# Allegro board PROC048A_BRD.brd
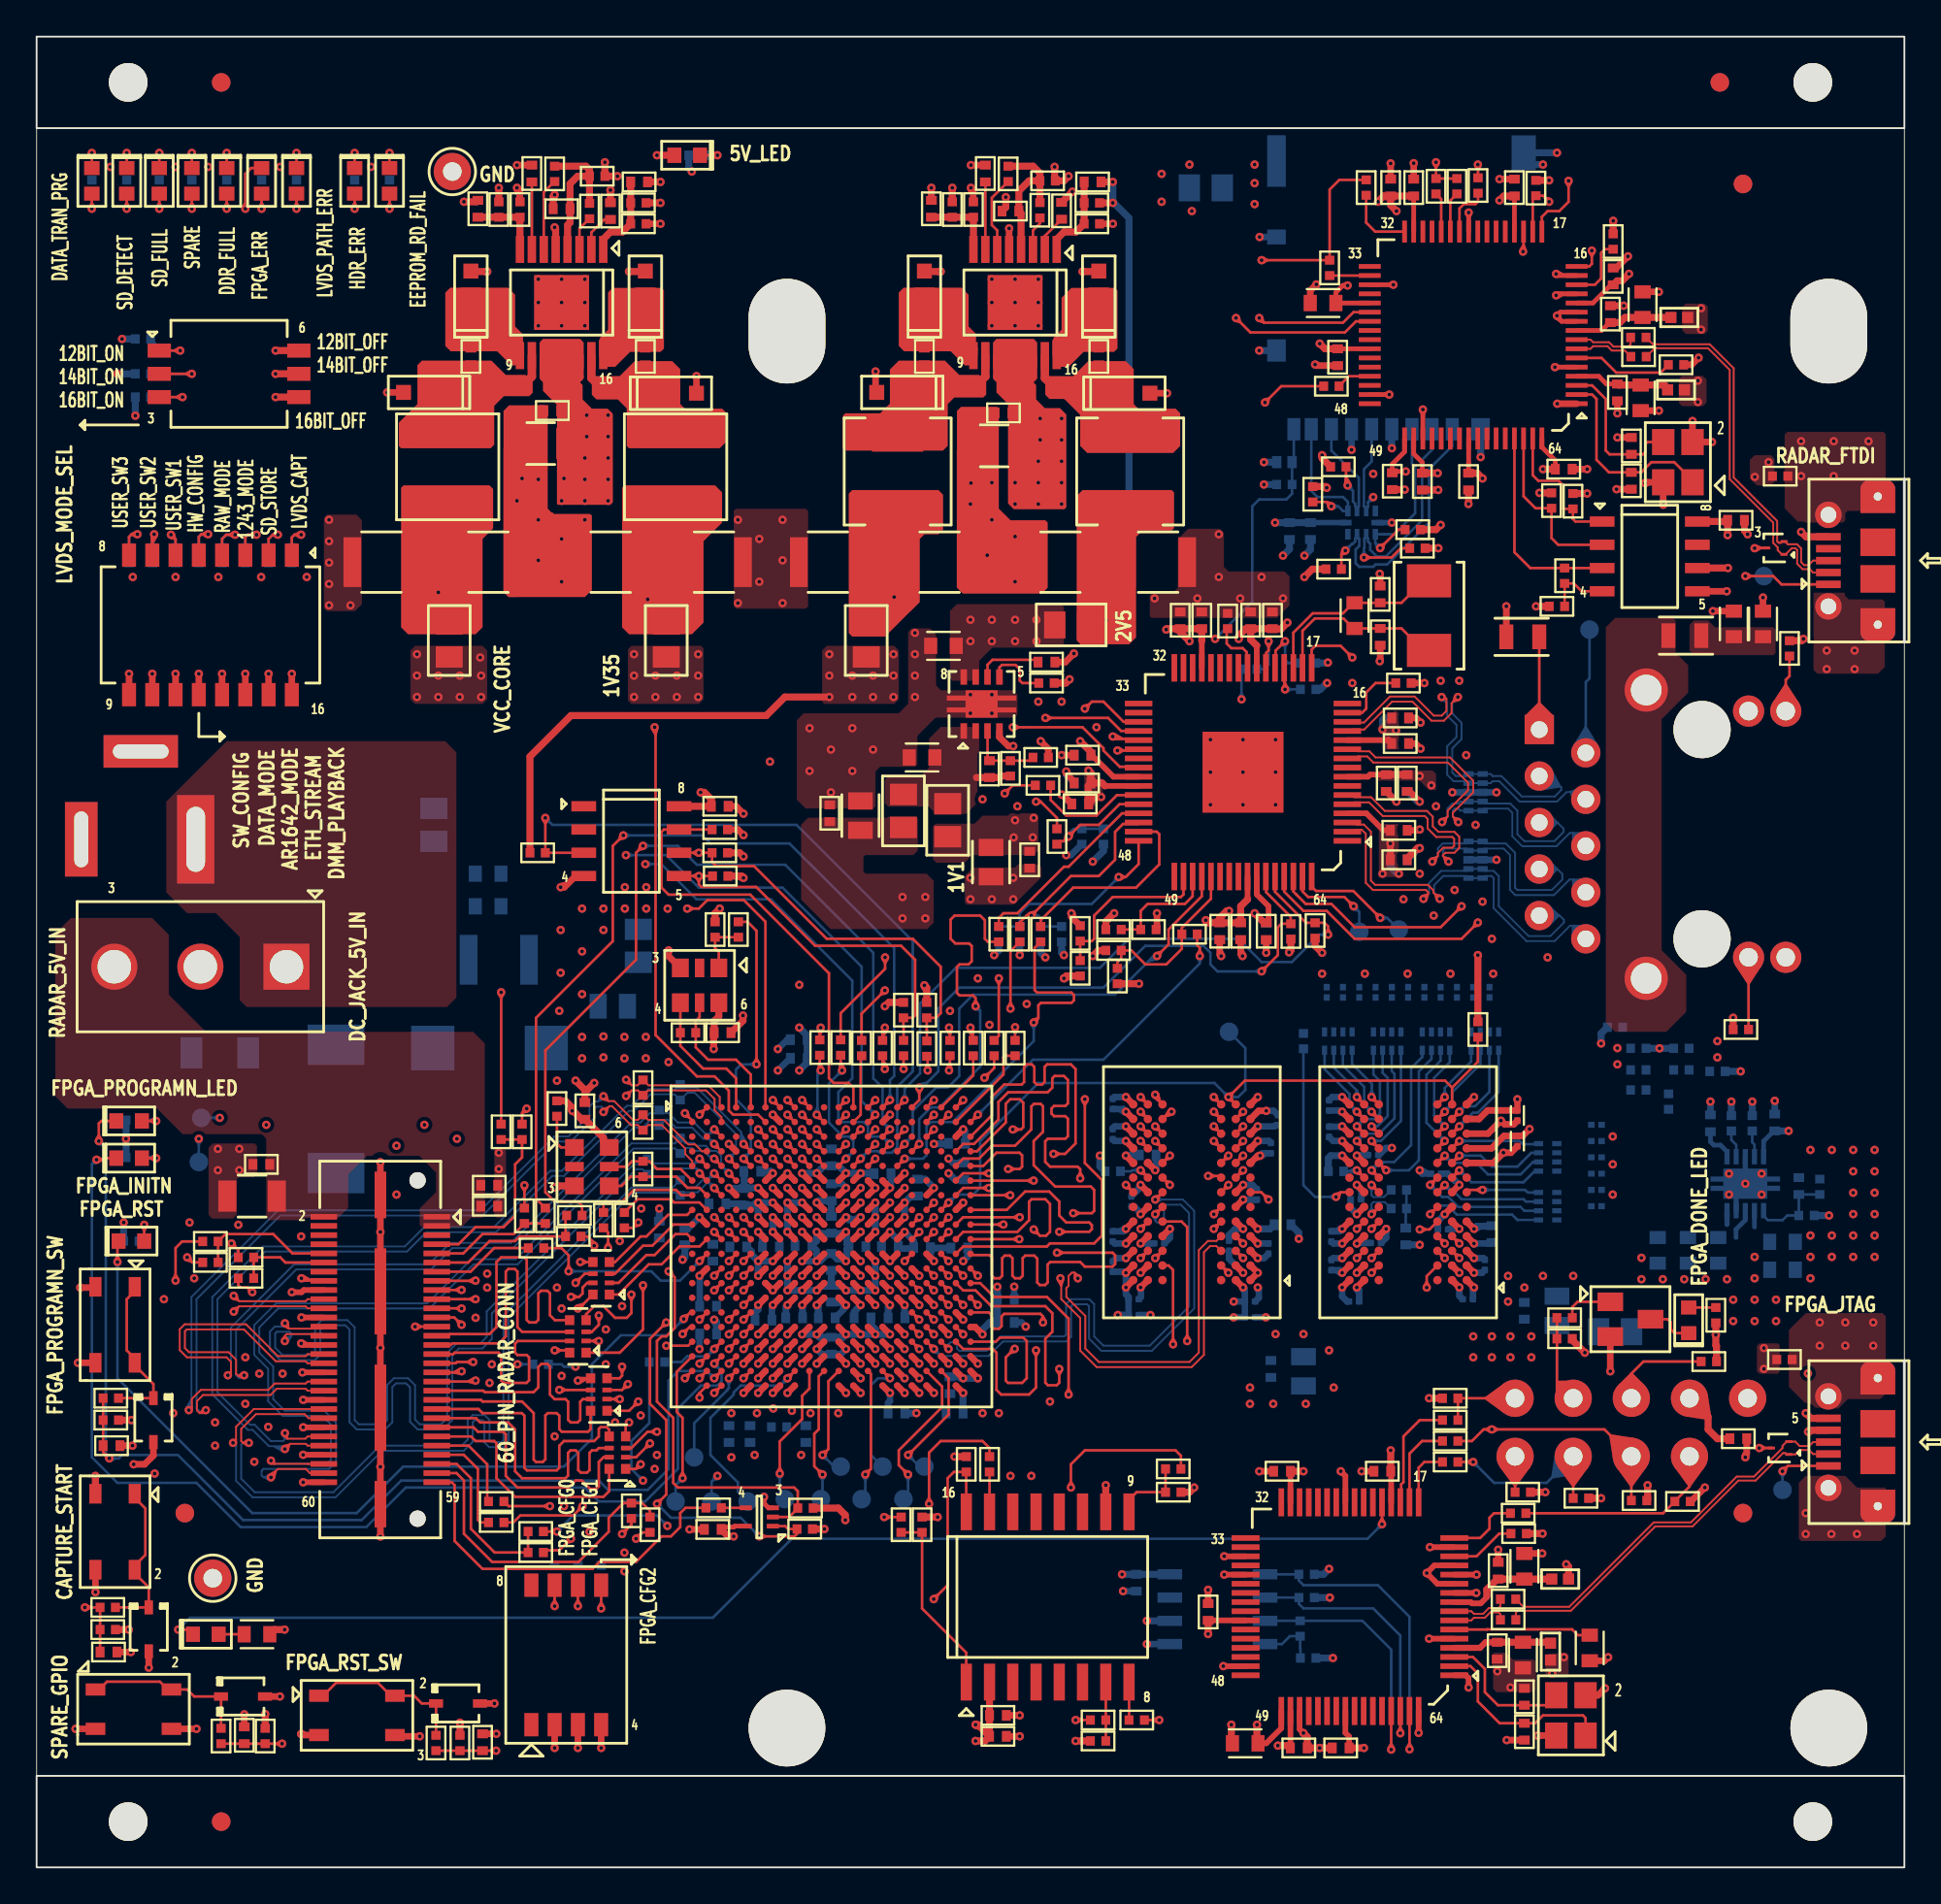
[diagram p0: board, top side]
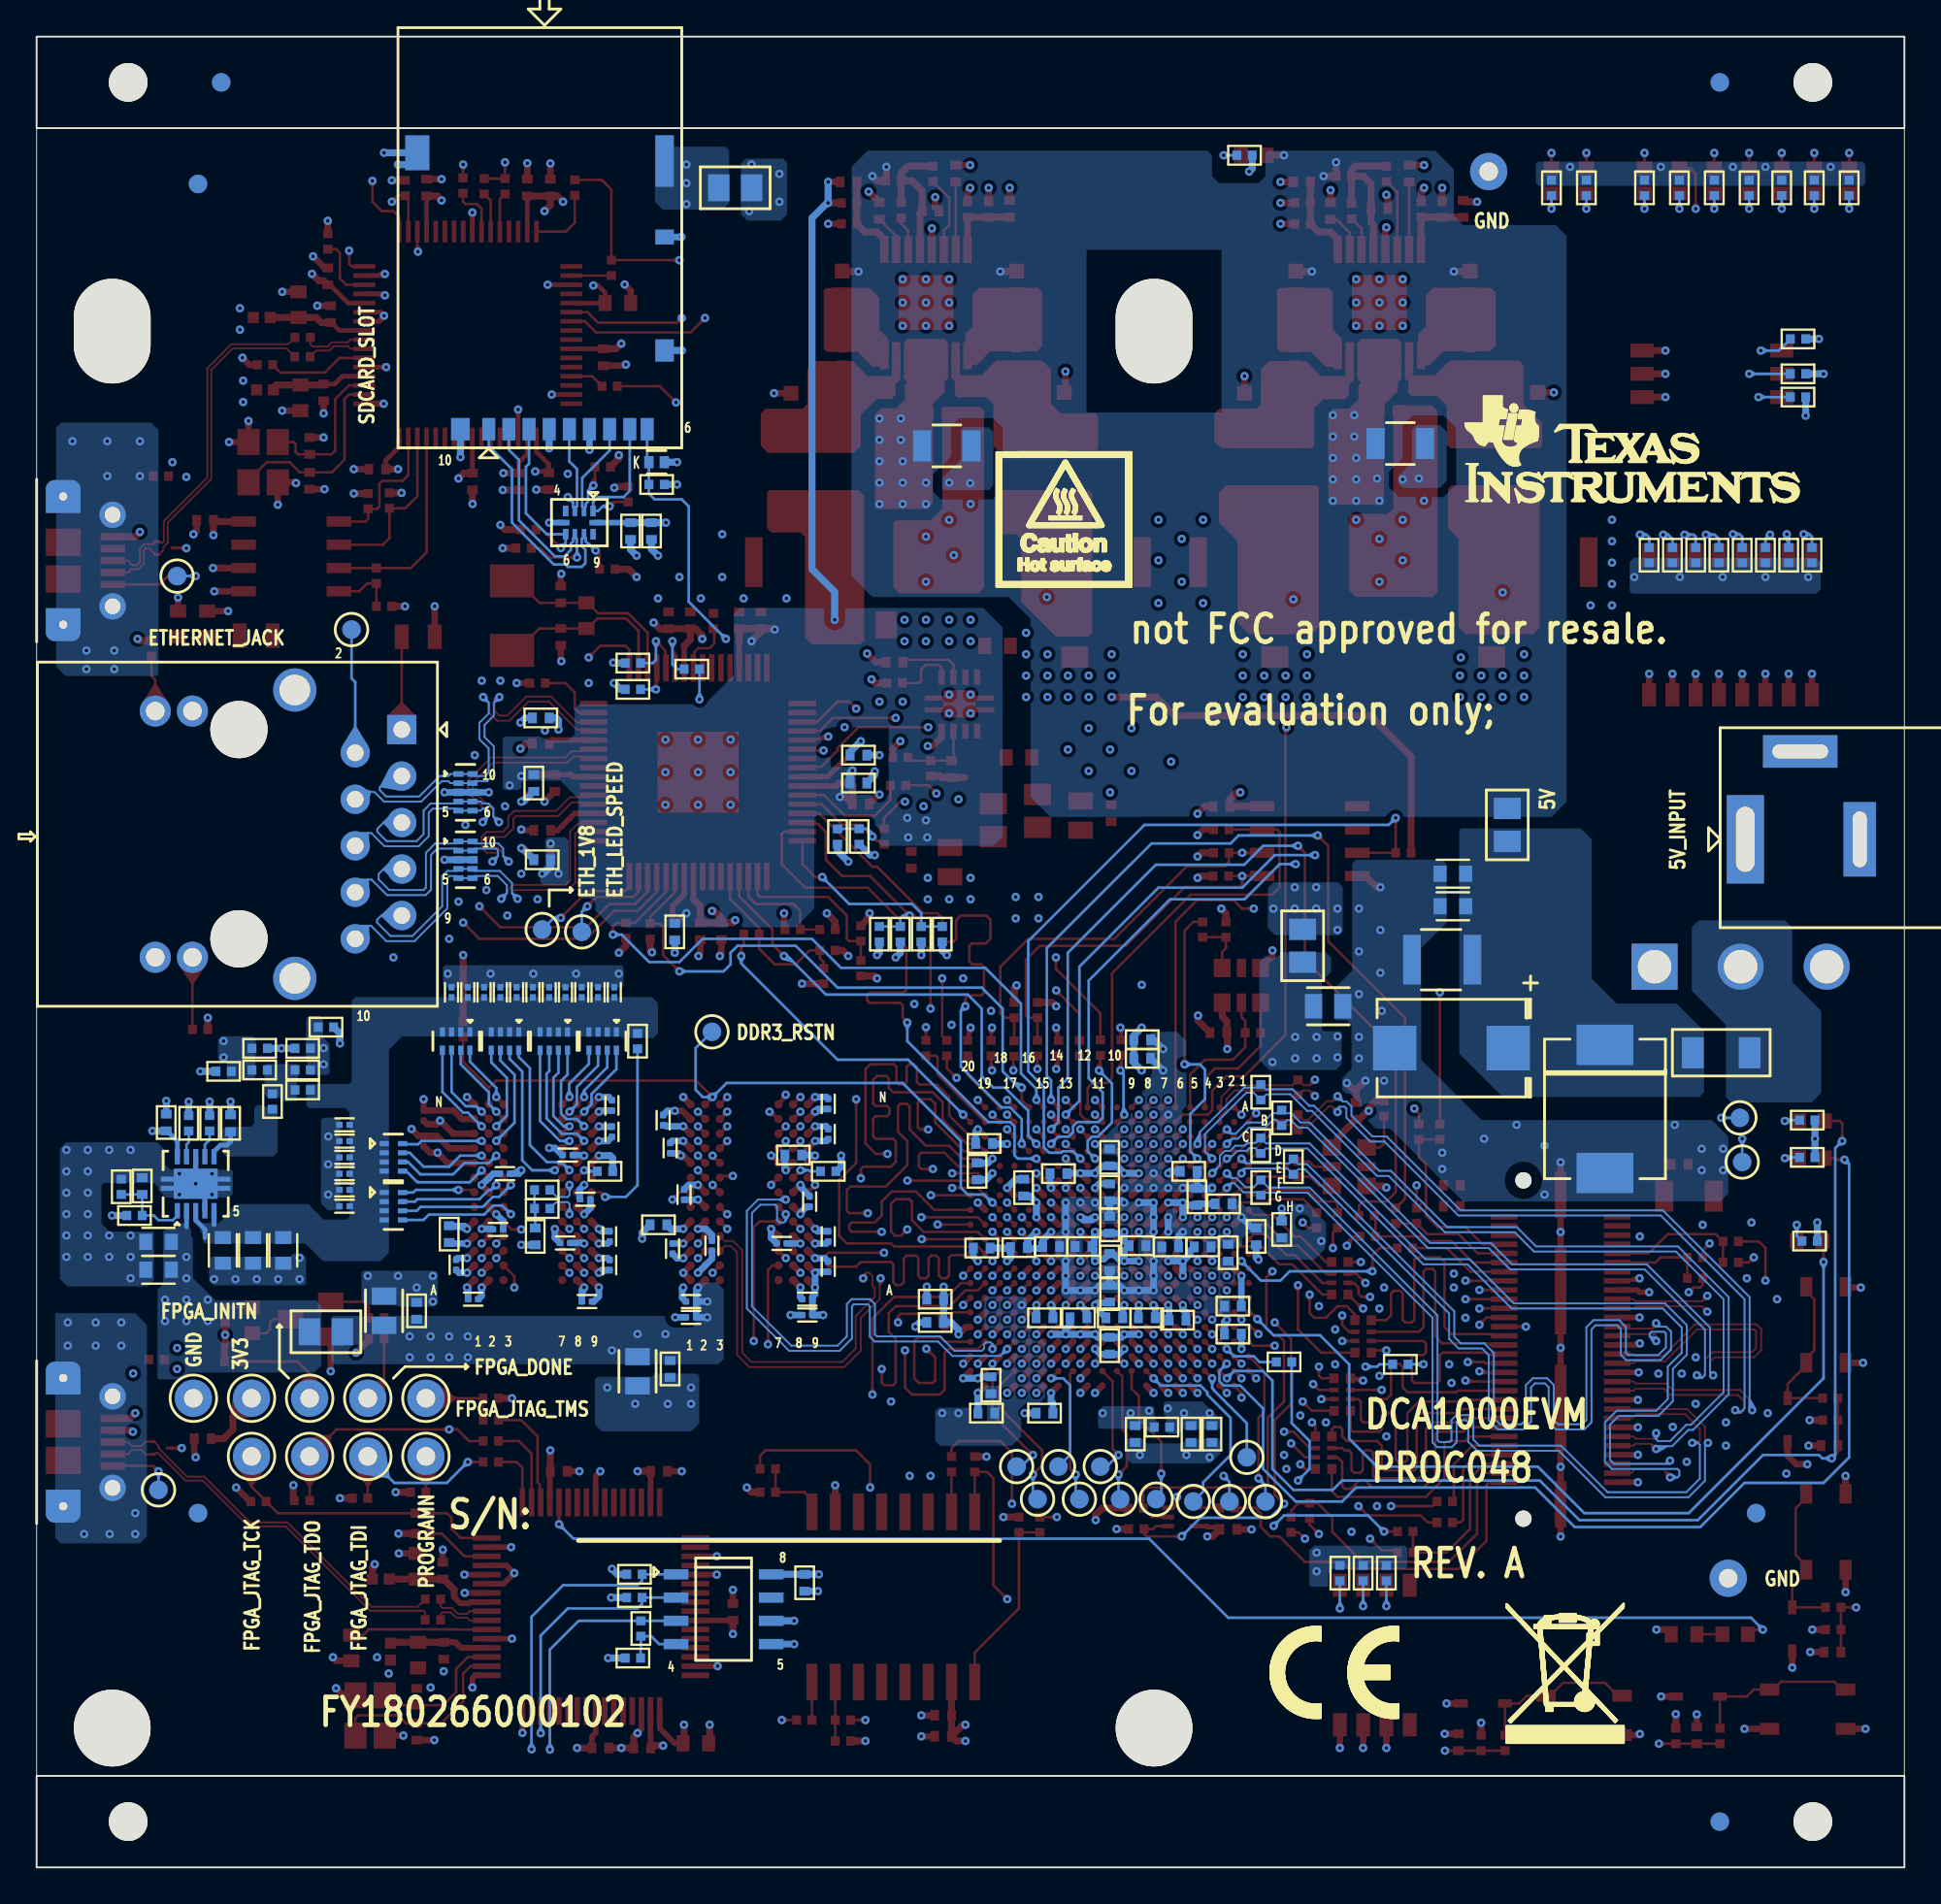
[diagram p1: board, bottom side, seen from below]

Outline 102 x 100 mm; copper layers: TOP, L02_GND1, L03_SIG1, L04_GND2, L05_PWR1, L06_PWR2, L07_GND3, L08_SIG2, L09_GND4, BOTTOM. Coordinates in mm from the lower left corner of the outline.
Outline path: rectangle 0,95 102,100 ; rectangle 0,0 102,5 ; 0,95 0,5 102,5 102,95 0,95

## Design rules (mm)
net group C_RGMII_RXC: nets C_RGMII_RXC RGMII_RXC
net group C_RGMII_RXD0: nets C_RGMII_RXD0 RGMII_RXD0
net group C_RGMII_RXD1: nets C_RGMII_RXD1 RGMII_RXD1
net group C_RGMII_RXD2: nets C_RGMII_RXD2 RGMII_RXD2
net group C_RGMII_RXD3: nets C_RGMII_RXD3 RGMII_RXD3
net group CONN_SPI_CLK: nets CONN_SPI_CLK RF_CONN_SPI_SCK
net group CONN_SPI_CSN: nets CONN_SPI_CSN RF_CONN_SPI_CS
net group CONN_SPI_MISO: nets CONN_SPI_MISO RF_CONN_SPI_MISO
net group CONN_SPI_MOSI: nets CONN_SPI_MOSI RF_CONN_SPI_MOSI
net group DMM_CLK: nets DMM_CLK DMM_CLK_C
net group DMM_MUX_CTL: nets DMM_MUX_CTL DMM_MUX_CTL_C
net group DMM_SYNC: nets DMM_SYNC DMM_SYNC_C
net group DP0: nets DP0 DP0_C
net group DP1: nets DP1 DP1_C
net group DP2: nets DP2 DP2_C
net group DP3: nets DP3 DP3_C
net group DP4: nets DP4 DP4_C
net group DP5: nets DP5 DP5_C
net group DP6: nets DP6 DP6_C
net group DP7: nets DP7 DP7_C
net group DP8: nets DP8 DP8_C
net group DP9: nets DP9 DP9_C
net group DP10: nets DP10 DP10_C
net group DP11: nets DP11 DP11_C
net group DP12: nets DP12 DP12_C
net group DP13: nets DP13 DP13_C
net group DP14: nets DP14 DP14_C
net group DP15: nets DP15 DP15_C
net group FTDI_USB1_DM_C: nets FTDI_USB1_DM FTDI_USB1_DM_C
net group FTDI_USB1_DP_C: nets FTDI_USB1_DP FTDI_USB1_DP_C
net group FTDI_USB2_DM: nets FTDI_USB2_DM FTDI_USB2_DM_C
net group FTDI_USB2_DP: nets FTDI_USB2_DP FTDI_USB2_DP_C
net group RGMII_TXC: nets N15802227 RGMII_TXC
net group RGMII_TXD0: nets N15802042 RGMII_TXD0
net group RGMII_TXD1: nets N15802046 RGMII_TXD1
net group RGMII_TXD2: nets N15802050 RGMII_TXD2
net group RGMII_TXD3: nets N15802054 RGMII_TXD3
net group SD_CLK: nets N15837897 SD_CLK
net group DDR_DATA0: nets DDR3_DM0 DDR3_DQ0 DDR3_DQ1 DDR3_DQ2 DDR3_DQ3 DDR3_DQ4 DDR3_DQ5 DDR3_DQ6 DDR3_DQ7 DDR3_DQS0 DDR3_DQS0N
net group DDR_DATA1: nets DDR3_DM1 DDR3_DQ8 DDR3_DQ9 DDR3_DQ10 DDR3_DQ11 DDR3_DQ12 DDR3_DQ13 DDR3_DQ14 DDR3_DQ15 DDR3_DQS1 DDR3_DQS1N
net group DIFFPAIR4: nets LVDS_CLKM

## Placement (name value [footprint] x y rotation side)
C1  12000pF  [CAP0402]  27.05 92.52 90 top
C2  0.22uF  [CAP0402]  28.67 90.6 180 top
C3  12000pF  [CAP0402]  51.81 92.52 90 top
C4  0.22uF  [CAP0402]  53.18 90.47 180 top
C5  0.027uF  [CAP0402]  32.9 92.06 180 top
C6  0.027uF  [CAP0402]  57.67 92.06 180 top
C7  1uF  [CAP0402_0-75]  73.95 91.75 90 top
C8  0.1uF  [CAP0402_0-75]  75.2 91.75 90 top
C9  0.1uF  [CAP0402_0-75]  80.7 91.75 90 top
C10  0.027uF  [CAP0402]  24.1 90.6 270 top
C11  0.027uF  [CAP0402]  48.86 90.6 270 top
C12  12000pF  [CAP0402]  31.34 90.47 90 top
C13  12000pF  [CAP0402]  55.97 90.48 90 top
C14  0.1uF  [CAP0402_0-75]  86.1 86.9 90 top
C15  4.7uF  [CAP0603_1]  70.25 85.45 180 top
C16  4.7uF  [CAP0603_1]  87.7 85.36 90 top
C17  0.1uF  [CAP0402_0-75]  85.95 84.84 90 top
C18  0.1uF  [CAP0402_0-75]  23.72 82.53 270 top
C19  0.1uF  [CAP0402_0-75]  33.24 82.53 270 top
C20  0.1uF  [CAP0402_0-75]  48.48 82.53 270 top
C21  0.1uF  [CAP0402_0-75]  58.01 82.53 270 top
C22  0.1uF  [CAP0402_0-75]  71.05 82.49 270 top
C23  0.1uF  [CAP0402_0-75]  86.33 80.56 270 top
C24  4.7uF  [CAP0603_1]  87.6 80.27 270 top
C25  0.1uF  [CAP0402_0-75]  28.16 79.57 0 top
C26  0.1uF  [CAP0402_0-75]  52.8 79.45 0 top
C27  10uF  [CAP1206]  27.53 77.77 180 top
C28  10uF  [CAP1206]  52.29 77.64 180 top
C29  8pF  [CAP0402]  87.09 77.64 90 top
C30  0.1uF  [CAP0402_0-75]  83.4 76.37 0 top
C31  8pF  [CAP0402]  87.09 75.74 270 top
C32  0.1uF  [CAP0402_0-75]  74.03 75.72 270 top
C33  0.1uF  [CAP0402_0-75]  75.67 75.7 270 top
C34  0.1uF  [CAP0402_0-75]  78.2 75.7 270 top
C35  0.1uF  [CAP0402_0-75]  92.8 73.58 0 top
C36  47uF  [CAP1210]  18.89 71.29 180 top
C37  47uF  [CAP1210]  24.61 71.29 0 top
C38  47uF  [CAP1210]  31.41 71.29 180 top
C39  47uF  [CAP1210]  36.92 71.29 0 top
C40  47uF  [CAP1210]  43.27 71.29 180 top
C41  47uF  [CAP1210]  49.24 71.29 0 top
C42  47uF  [CAP1210]  55.97 71.29 180 top
C43  47uF  [CAP1210]  61.18 71.29 0 top
C44  27pF  [CAP0402]  73.37 69.53 90 top
C45  1000pF  [CAP0402_0-75]  62.45 68.12 90 top
C46  1000pF  [CAP0402_0-75]  63.63 68.12 90 top
C47  10000pF  [CAP0402]  66.3 68.12 90 top
C48  10uF  [CAP0402_0-75]  67.49 68.12 90 top
C49  0.1uF  [CAP0603_1]  92.69 67.92 270 top
C50  0.1uF  [CAP0603_1]  94.28 67.92 270 top
C51  27pF  [CAP0402]  73.37 67.21 270 top
C52  10uF  [CAP0603_1]  49.52 66.72 180 top
C53  0.47uF  [CAP0402]  55.15 65.83 0 top
C54  0.1uF  [CAP0402_0-75]  74.47 62.78 0 top
C55  10000pF  [CAP0402]  74.47 61.39 0 top
C56  0.1uF  [CAP0402_0-75]  57.12 60.75 180 top
C57  10uF  [CAP0603_1]  48.35 60.63 180 top
C58  0.47uF  [CAP0402]  52.04 59.99 90 top
C59  10000pF  [CAP0402]  73.7 59.23 270 top
C60  0.1uF  [CAP0402_0-75]  74.85 59.23 270 top
C61  1000pF  [CAP0402_0-75]  57.12 59.23 180 top
C62  0.1uF  [CAP0402_0-75]  37.31 57.96 0 top
C63  1uF  [CAP0402_0-75]  43.32 57.58 90 top
C64  22uF  [CAP0805_1-5]  44.99 57.45 90 top
C65  0.1uF  [CAP0402_0-75]  74.39 56.65 0 top
C66  1uF  [CAP0402_0-75]  54.23 55.04 270 top
C67  1uF  [CAP0402_0-75]  74.39 55.04 0 top
C68  22uF  [CAP0805_1-5]  52.12 54.91 270 top
C69  1uF  [CAP0402_0-75]  64.61 51.14 270 top
C70  0.1uF  [CAP0402_0-75]  65.75 51.14 270 top
C71  1000pF  [CAP0402_0-75]  67.15 51.14 270 top
C72  0.01uF  [CAP0402_0-75]  37.46 45.59 0 top
C73  0.01uF  [CAP0402_0-75]  29.94 41.32 90 top
C74  0.1uF  [CAP0201]  80.87 41.07 90 top
C75  0.1uF  [CAP0201]  80.87 39.67 90 top
C76  1uF  [CAP0402_0-75]  12.27 38.4 180 top
C77  0.01uF  [CAP0402_0-75]  24.72 37.26 0 top
C78  10uF  [CAP1206]  11.76 36.66 180 top
C79  0.1uF  [CAP0402_0-75]  24.72 36.11 180 top
C80  0.1uF  [CAP0402_0-75]  92.93 23.41 180 top
C81  0.1uF  [CAP0402_0-75]  4.09 23.03 180 top
C82  0.1uF  [CAP0402_0-75]  68.01 21.64 180 top
C83  0.1uF  [CAP0402_0-75]  73.49 21.64 180 top
C84  0.1uF  [CAP0402_0-75]  36.92 18.46 0 top
C85  4.7uF  [CAP0603_1]  81.25 16.45 90 top
C86  0.1uF  [CAP0402_0-75]  79.82 16.21 90 top
C87  0.1uF  [CAP0402_0-75]  63.98 13.95 90 top
C88  0.1uF  [CAP0402_0-75]  79.76 11.84 270 top
C89  0.1uF  [CAP0402_0-75]  3.93 11.76 180 top
C90  4.7uF  [CAP0603_1]  81.17 11.6 270 top
C91  8pF  [CAP0402]  81.25 9.32 90 top
C92  10000pF  [CAP0402]  52.5 8.3 0 top
C93  8pF  [CAP0402]  81.25 7.41 270 top
C94  0.1uF  [CAP0402_0-75]  52.5 7.16 0 top
C95  0.1uF  [CAP0402_0-75]  11.34 7.22 270 top
C96  0.1uF  [CAP0402_0-75]  24.35 6.84 270 top
C97  3.3uF  [CAP0603_1]  66 6.78 180 top
C98  0.1uF  [CAP0402_0-75]  68.93 6.52 0 top
C99  10uF  [CAP1206]  27.53 77.77 180 bottom
C100  10uF  [CAP1206]  52.29 77.64 180 bottom
C101  0.1uF  [CAP0402_0-75]  69.56 72.99 270 bottom
C102  4.7uF  [CAP0402_0-75]  68.42 72.99 270 bottom
C103  1uF  [CAP0402_0-75]  74.47 62.78 0 bottom
C104  1uF  [CAP0402_0-75]  57.12 60.75 180 bottom
C105  0.1uF  [CAP0402_0-75]  74.85 59.23 270 bottom
C106  0.1uF  [CAP0402_0-75]  56.99 58.09 180 top
C107  0.1uF  [CAP0402_0-75]  57.12 59.23 180 bottom
C108  10uF  [CAP0402_0-75]  74.39 55.04 0 bottom
C109  10uF  [CAP0603_1]  24.66 54.28 0 bottom
C110  10uF  [CAP0603_1]  24.66 52.5 0 bottom
C111  10uF  [CAP0402_0-75]  67.15 51.1 270 bottom
C112  100uF  [CAP1210]  25.24 49.58 0 bottom
C113  0.01uF  [CAP0201_0-5]  79.34 47.8 90 bottom
C114  0.01uF  [CAP0201_0-5]  78.45 47.8 90 bottom
C115  0.01uF  [CAP0201_0-5]  77.56 47.8 90 bottom
C116  0.1uF  [CAP0201]  76.68 47.8 270 bottom
C117  0.01uF  [CAP0201_0-5]  75.79 47.8 90 bottom
C118  0.1uF  [CAP0201]  74.9 47.8 270 bottom
C119  0.1uF  [CAP0201]  74.01 47.8 270 bottom
C120  0.1uF  [CAP0201]  73.12 47.8 270 bottom
C121  0.01uF  [CAP0201_0-5]  72.23 47.8 90 bottom
C122  0.1uF  [CAP0201]  71.34 47.8 270 bottom
C123  0.01uF  [CAP0201_0-5]  70.45 47.8 90 bottom
C124  22uF  [CAP0805_1-5]  31.46 47.04 180 bottom
C125  0.1uF  [CAP0402_0-75]  41.62 45.21 0 bottom
C126  47uF  [CAPT7343D_3-25]  24.73 44.75 0 bottom
C127  0.1uF  [CAP0402_0-75]  41.62 44.19 0 bottom
C128  0.1uF  [CAP0201]  58.77 41.7 270 bottom
C129  0.01uF  [CAP0201_0-5]  70.58 41.62 90 bottom
C130  0.01uF  [CAP0201_0-5]  67.79 40.81 270 bottom
C131  4.7uF  [CAP0402_0-75]  94.92 40.69 90 bottom
C132  0.1uF  [CAP0402_0-75]  91.41 40.65 270 bottom
C133  0.1uF  [CAP0201]  85.18 40.56 180 bottom
C134  0.1uF  [CAP0201]  70.58 40.18 270 bottom
C135  0.01uF  [CAP0201_0-5]  58.77 40.05 90 bottom
C136  0.01uF  [CAP0201_0-5]  85.18 39.67 0 bottom
C137  0.1uF  [CAP0402_0-75]  50.26 39.54 180 bottom
C138  0.1uF  [CAP0201]  67.4 39.29 90 bottom
C139  0.01uF  [CAP0201_0-5]  72.99 38.91 0 bottom
C140  0.1uF  [CAP0402_0-75]  60.67 38.91 0 bottom
C141  0.01uF  [CAP0201_0-5]  85.18 38.78 0 bottom
C142  0.1uF  [CAP0402_0-75]  43.4 38.78 270 bottom
C143  0.1uF  [CAP0402_0-75]  50.64 38.02 270 bottom
C144  0.01uF  [CAP0402_0-75]  39.08 38.02 180 bottom
C145  0.1uF  [CAP0201]  85.18 37.89 180 bottom
C146  0.1uF  [CAP0201]  76.42 37.89 0 bottom
C147  0.01uF  [CAP0402_0-75]  46.2 37.89 0 bottom
C148  0.1uF  [CAP0402_0-75]  96.23 37.22 270 bottom
C149  0.1uF  [CAP0402_0-75]  48.1 37.13 270 bottom
C150  0.1uF  [CAP0201]  85.18 37 180 bottom
C151  0.1uF  [CAP0402_0-75]  43.4 36.88 270 bottom
C152  0.01uF  [CAP0201_0-5]  66.64 36.75 270 bottom
C153  0.1uF  [CAP0402_0-75]  38.64 36.62 270 bottom
C154  0.01uF  [CAP0201_0-5]  72.04 36.5 180 bottom
C155  0.01uF  [CAP0201_0-5]  59.78 36.37 270 bottom
C156  0.01uF  [CAP0402_0-75]  37.18 36.24 180 bottom
C157  0.01uF  [CAP0201_0-5]  85.18 36.11 0 bottom
C158  0.1uF  [CAP0402_0-75]  34 34.84 90 bottom
C159  0.01uF  [CAP0402_0-75]  68.04 35.1 0 bottom
C160  0.01uF  [CAP0402_0-75]  43.4 35.1 270 bottom
C161  0.1uF  [CAP0201]  76.8 34.84 0 bottom
C162  0.1uF  [CAP0402_0-75]  79.47 34.59 90 bottom
C163  0.01uF  [CAP0402_0-75]  74.77 34.46 270 bottom
C164  0.1uF  [CAP0201]  70.71 34.46 90 bottom
C165  0.01uF  [CAP0201_0-5]  58.77 34.46 270 bottom
C166  0.1uF  [CAP0402_0-75]  35.4 34.46 270 bottom
C167  10uF  [CAP0603_1]  95.34 34.17 0 bottom
C168  0.1uF  [CAP0201]  73.14 34.11 0 bottom
C169  0.1uF  [CAP0201]  61.31 34.08 0 bottom
C170  0.1uF  [CAP0201]  65.12 33.96 90 bottom
C171  0.1uF  [CAP0402_0-75]  41.88 33.96 180 bottom
C172  0.01uF  [CAP0402_0-75]  46.6 33.91 0 bottom
C173  0.1uF  [CAP0402_0-75]  44.83 33.91 0 bottom
C174  0.01uF  [CAP0402_0-75]  40.1 33.89 180 bottom
C175  0.01uF  [CAP0402_0-75]  38.32 33.89 180 bottom
C176  0.1uF  [CAP0402_0-75]  48.35 33.85 0 bottom
C177  0.01uF  [CAP0402_0-75]  50.39 33.83 0 bottom
C178  0.01uF  [CAP0201_0-5]  67.27 33.8 90 bottom
C179  10uF  [CAP0603_1]  91.83 33.7 270 bottom
C180  10uF  [CAP0603_1]  90.18 33.7 270 bottom
C181  10uF  [CAP0603_1]  88.53 33.7 270 bottom
C182  0.01uF  [CAP0402_0-75]  36.92 33.57 90 bottom
C183  0.01uF  [CAP0402_0-75]  43.4 33.07 90 bottom
C184  0.1uF  [CAP0201]  79.09 32.91 90 bottom
C185  0.1uF  [CAP0201]  70.71 32.9 270 bottom
C186  0.01uF  [CAP0201_0-5]  58.77 32.81 90 bottom
C187  10uF  [CAP0603_1]  95.34 32.64 0 bottom
C188  0.1uF  [CAP0402_0-75]  43.4 31.34 90 bottom
C189  0.01uF  [CAP0201_0-5]  78.16 31.03 0 bottom
C190  0.01uF  [CAP0201_0-5]  59.91 31.03 0 bottom
C191  0.1uF  [CAP0402_0-75]  52.93 31.03 180 bottom
C192  0.1uF  [CAP0201]  71.94 30.91 180 bottom
C193  0.01uF  [CAP0201_0-5]  66.26 30.91 0 bottom
C194  0.1uF  [CAP0402_0-75]  36.67 30.65 0 bottom
C195  22uF  [CAP0805_1-5]  83.03 30.4 90 bottom
C196  1uF  [CAP0402_0-75]  81.25 30.4 90 bottom
C197  0.01uF  [CAP0201_0-5]  59.91 30.17 0 bottom
C198  0.01uF  [CAP0201_0-5]  66.26 30.04 0 bottom
C199  1nF  [CAP0402_0-75]  46.96 30.02 180 bottom
C200  0.1uF  [CAP0402_0-75]  45.1 30.02 0 bottom
C201  0.01uF  [CAP0402_0-75]  43.15 30.02 0 bottom
C202  0.1uF  [CAP0402_0-75]  41.37 30.02 0 bottom
C203  1uF  [CAP0402_0-75]  39.69 29.89 0 bottom
C204  0.01uF  [CAP0402_0-75]  52.93 29.76 0 bottom
C205  0.01uF  [CAP0402_0-75]  36.67 29.13 180 bottom
C206  0.1uF  [CAP0402_0-75]  43.4 28.49 90 bottom
C207  1uF  [CAP0402_0-75]  67.4 27.22 270 bottom
C208  22uF  [CAP0805_1-5]  69.18 27.1 270 bottom
C209  0.1uF  [CAP0402_0-75]  46.96 24.81 0 bottom
C210  0.1uF  [CAP0402_0-75]  42 23.67 90 bottom
C211  0.1uF  [CAP0402_0-75]  38.96 23.67 90 bottom
C212  0.1uF  [CAP0402_0-75]  37.81 23.67 90 bottom
C213  0.01uF  [CAP0402_0-75]  49.88 26.34 90 bottom
C214  0.1uF  [CAP0402_0-75]  50.13 24.81 180 bottom
C215  0.1uF  [CAP0402_0-75]  60.06 15.55 270 bottom
C216  0.1uF  [CAP0402_0-75]  71.21 6.52 180 top
D1  PD3S230HQ-7  [DIO_POWERDI-323_0-7]  23.72 86.24 180 top
D2  PD3S230HQ-7  [DIO_POWERDI-323_0-7]  33.24 86.24 180 top
D3  PD3S230HQ-7  [DIO_POWERDI-323_0-7]  48.48 86.24 180 top
D4  PD3S230HQ-7  [DIO_POWERDI-323_0-7]  58.01 86.24 180 top
D5  PD3S230HQ-7  [DIO_POWERDI-323_0-7]  20.99 80.56 270 top
D6  PD3S230HQ-7  [DIO_POWERDI-323_0-7]  46.83 80.56 270 top
D7  PD3S230HQ-7  [DIO_POWERDI-323_0-7]  35.08 80.52 90 top
D8  PD3S230HQ-7  [DIO_POWERDI-323_0-7]  59.85 80.52 90 top
D9  TPD2EUSB30DRTR  [SOT-3]  94.95 72.07 180 top
D10  SD05C-01FTG  [DIO_SOD323]  6.38 24.43 270 top
D11  TPD2EUSB30DRTR  [SOT-3]  95.22 22.91 180 top
D12  SD05C-01FTG  [DIO_SOD323]  6.12 13 270 top
D13  SD05C-01FTG  [DIO_SOD323]  11.27 9.34 0 top
D14  SD05C-01FTG  [DIO_SOD323]  23.01 8.95 0 top
D15  TPD1E10B06DPY  [DIO_DFN0402]  68.14 76.75 180 bottom
D16  SMCJ64CA  [DIO_SMC]  16.35 41.43 270 bottom
F1  5A  [FUSE_1206]  10 44.5 0 bottom
FB1  60E  [IND0402]  89.71 84.66 180 top
FB2  60E  [IND0402]  89.53 80.7 180 top
FB3  60E  [IND0402]  83.2 15.75 180 top
FB4  60E  [IND0402]  82.67 11.79 90 top
FL1  30E  [EMIFIL_BLM21P_0805_1-1]  56.5 67.86 180 top
FL2  30E  [EMIFIL_BLM21P_0805_1-1]  22.53 67.02 270 top
FL3  30E  [EMIFIL_BLM21P_0805_1-1]  34.38 67.02 270 top
FL4  30E  [EMIFIL_BLM21P_0805_1-1]  45.31 67.02 270 top
FL5  30E  [EMIFIL_BLM21P_0805_1-1]  47.34 57.7 270 top
FL6  30E  [EMIFIL_BLM21P_0805_1-1]  49.75 57.2 270 top
FL7  30E  [EMIFIL_BLM21P_0805_1-1]  63.85 91.74 0 bottom
FL8  30E  [EMIFIL_BLM21P_0805_1-1]  21.68 56.94 90 bottom
FL9  30E  [EMIFIL_BLM21P_0805_1-1]  32.86 50.34 90 bottom
FL10  30E  [EMIFIL_BLM21P_0805_1-1]  86.2 29.26 180 bottom
J1  CON_USB-B_5_F  [CON_USBB5_105017-01_S_R_S_2-6]  100.03 71.38 90 top
J2  RAPC722  [CON_PWRJACK3_RAPC722_P_R_T]  8.66 56.15 90 bottom
J3  CON_PMC_2X30_M  [CON_PMC2X30_QTH-30_P_S_S_4-3]  18.76 28.29 270 top
J4  CON_USB-B_5_F  [CON_USBB5_105017-01_S_R_S_2-6]  100.03 23.23 90 top
J5  DM3AT-SF-PEJM5  [CON_SD8_DM3AT-SF_S_R_S_1-7]  74.01 85.88 0 bottom
J6  CON_RJ45-14_LPJG16414A4NL  [CON_RJ45-14_LPJG16414A4NL_S_R_T_13-5]  82.06 62.15 270 bottom
L1  4.7uH  [IND_NRS5020_200X200_SMD_3-1]  22.45 76.5 180 top
L2  4.7uH  [IND_NRS5020_200X200_SMD_3-1]  34.89 76.5 180 top
L3  10uH  [IND_IHLP2020CZ_230X215_SMD]  47.02 76.25 270 top
L4  10uH  [IND_IHLP2020CZ_230X215_SMD]  59.72 76.25 270 top
LD1  LTST-C190KGKT  [LED_0603_0-8]  3.02 92.12 270 top
LD2  LTST-C190KGKT  [LED_0603_0-8]  4.92 92.12 270 top
LD3  LTST-C190KRKT  [LED_0603]  6.7 92.12 270 top
LD4  LTST-C190KGKT  [LED_0603_0-8]  8.48 92.12 270 top
LD5  LTST-C190KRKT  [LED_0603]  12.29 92.12 270 top
LD6  LTST-C190KRKT  [LED_0603]  10.38 92.12 270 top
LD7  LTST-C190KRKT  [LED_0603]  14.19 92.12 270 top
LD8  LTST-C190KRKT  [LED_0603]  17.37 92.12 270 top
LD9  LTST-C190KRKT  [LED_0603]  19.27 92.12 270 top
LD10  LTST-C190KGKT  [LED_0603_0-8]  35.53 93.52 180 top
LD11  LTST-C190KRKT  [LED_0603]  5.05 40.77 0 top
LD12  LTST-C190KRKT  [LED_0603]  5.05 38.74 0 top
LD13  LTST-C190KRKT  [LED_0603]  5.17 34.21 0 top
LD14  LTST-C190KGKT  [LED_0603_0-8]  90.22 29.88 90 top
LD15  LTST-C191KGKT  [LED_0603]  9.24 12.73 0 top
NOREF  -  []  -14.89 -67.14 0 top
NOREF#2  -  []  0 0 90 top
NOREF#3  -  [unnamed#2]  10.08 2.5 0 top
NOREF#4  -  [unnamed#2]  40.98 7.61 0 top
NOREF#5  -  []  -338.36 -84.45 0 top
NOREF#6  -  []  97.87 7.61 90 top
NOREF#7  -  [unnamed#2]  91.92 97.5 0 top
NOREF#8  -  [unnamed#2]  97 97.5 0 top
NOREF#9  -  []  40.98 83.91 0 top
NOREF#10  -  []  0 5 90 top
NOREF#11  -  [unnamed#2]  40.98 83.91 0 top
NOREF#12  -  [unnamed#2]  93.19 19.35 0 top
NOREF#13  -  [unnamed#2]  8.1 19.35 0 top
NOREF#14  -  []  50.51 23.54 0 top
NOREF#15  -  []  -87.39 -56.45 0 top
NOREF#16  -  [unnamed#2]  97.87 7.61 0 top
NOREF#17  -  [unnamed#2]  10.08 97.5 0 top
NOREF#18  -  []  49.09 -45.09 0 top
NOREF#19  -  []  97.87 7.61 0 top
NOREF#20  -  []  0 95 0 top
NOREF#21  -  [unnamed#2]  5 97.5 0 top
NOREF#22  -  [unnamed#2]  5 2.5 0 top
NOREF#23  -  []  -337.09 -104.09 0 top
NOREF#24  -  [unnamed#2]  93.19 91.95 0 top
NOREF#25  -  [unnamed#2]  97.87 83.91 0 top
NOREF#26  -  [unnamed#2]  97 2.5 0 top
NOREF#27  -  []  102 5 90 top
NOREF#28  -  [unnamed#2]  8.1 19.35 180 bottom
NOREF#29  -  [unnamed#2]  91.92 97.5 180 bottom
NOREF#30  -  [unnamed#2]  10.08 97.5 180 bottom
NOREF#31  -  [unnamed#2]  10.08 2.5 180 bottom
NOREF#32  -  [unnamed#2]  93.19 19.35 180 bottom
NOREF#33  -  [unnamed#2]  93.19 91.95 180 bottom
Q1  MMBT3904-7-F  [TO_SOT23-123]  87.04 29.94 270 top
R1  10E  [RES0402]  30.61 92.38 0 top
R2  10E  [RES0402]  55.21 92.12 0 top
R3  0E  [RES0402]  78.72 91.87 270 top
R4  0E  [RES0402]  76.42 91.83 270 top
R5  0E  [RES0402]  77.56 91.83 270 top
R6  0E  [RES0402]  72.61 91.75 270 top
R7  10K  [RES0402_0-5]  81.88 91.73 270 top
R8  10K  [RES0402_0-5]  28.29 92.5 270 top
R9  10K  [RES0402_0-5]  53.05 92.5 270 top
R10  3.92K  [RES0402_0-5]  32.86 90.92 180 top
R11  10K  [RES0402_0-5]  57.63 90.92 180 top
R12  1.91K  [RES0402]  25.24 90.56 270 top
R13  2.21K  [RES0402]  26.4 90.56 90 top
R14  10K  [RES0402_0-5]  50.01 90.56 270 top
R15  2.21K  [RES0402]  51.16 90.56 90 top
R16  10K  [RES0402_0-5]  30.19 90.47 270 top
R17  10K  [RES0402_0-5]  54.79 90.52 270 top
R18  3.16K  [RES0402]  32.86 89.78 0 top
R19  3.16K  [RES0402]  57.63 89.78 0 top
R20  4.7K  [RES0402]  86.1 88.81 270 top
R21  1K  [RES0402]  36.04 93.52 180 bottom
R22  0E  [RES0402]  70.61 87.37 270 top
R23  0E  [RES0402]  87.47 83.57 180 top
R24  0E  [RES0402]  87.48 82.52 180 top
R25  10K  [RES0402_0-5]  89.53 82.08 180 top
R26  0E  [RES0402]  70.71 80.9 0 top
R27  0E  [RES0402]  95.22 75.99 0 top
R28  10K  [RES0402_0-5]  71.09 76.5 0 top
R29  10K  [RES0402_0-5]  69.69 75 270 top
R30  10K  [RES0402_0-5]  82.73 74.66 270 top
R31  10K  [RES0402_0-5]  83.9 74.62 270 top
R32  10K  [RES0402_0-5]  75.15 73.07 180 top
R33  10K  [RES0402_0-5]  75.41 72.06 180 top
R34  10K  [RES0402_0-5]  70.83 70.91 0 top
R35  2.2K  [RES0402_0-5]  83.45 70.55 90 top
R37  10K  [RES0402_0-5]  83.03 68.88 0 top
R38  1M  [RES0603_0-75]  71.98 68.37 270 top
R39  4.7K  [RES0402]  65.04 68.08 90 top
R40  220E  [RES0402_0-5]  95.73 66.58 270 top
R41  0E  [RES0805]  90.01 67.28 180 top
R42  0E  [RES0805]  81.16 67.21 0 top
R43  0E  [RES0402]  55.15 64.69 180 top
R44  11K  [RES0402_0-5]  74.64 64.69 0 top
R45  1.91K  [RES0402]  53.18 60.03 90 top
R46  5.11K  [RES0402]  54.83 60.63 0 top
R47  22E  [RES0402]  54.96 59.1 0 top
R48  0E  [RES0402]  55.72 56.31 90 top
R49  10K  [RES0402_0-5]  37.31 56.69 0 top
R50  10K  [RES0402_0-5]  27.36 55.42 0 top
R51  2.2K  [RES0402_0-5]  37.31 55.42 180 top
R52  2.2K  [RES0402_0-5]  37.33 54.15 180 top
R53  10K  [RES0402_0-5]  37.05 51.23 270 top
R54  0E  [RES0402]  38.32 51.23 270 top
R55  11K  [RES0402_0-5]  58.81 51.23 180 top
R56  2.49K  [RES0402]  60.72 51.23 180 top
R57  4.7K  [RES0402]  68.5 51.12 90 top
R58  2.2K  [RES0402_0-5]  69.82 51.18 90 top
R59  2.49K  [RES0402]  56.99 51.02 270 top
R60  0E  [RES0402]  52.55 50.97 270 top
R61  0E  [RES0402]  53.69 50.97 270 top
R62  0E  [RES0402]  54.83 50.97 270 top
R63  0E  [RES0402]  62.96 50.97 180 top
R64  6.04K  [RES0402]  58.81 50.08 0 top
R65  11K  [RES0402_0-5]  56.99 49.11 270 top
R66  2.49K  [RES0402]  59.02 48.69 90 top
R67  10K  [RES0402_0-5]  47.34 46.83 270 top
R68  10K  [RES0402_0-5]  48.61 46.83 270 top
R69  10K  [RES0402_0-5]  78.71 45.77 270 top
R70  220E  [RES0402_0-5]  93.07 45.77 0 top
R71  100E  [RES0402]  35.57 45.59 0 top
R72  22E  [RES0402]  42.77 44.78 90 top
R73  0E  [RES0402]  43.91 44.78 270 top
R74  22E  [RES0402]  45.05 44.75 270 top
R75  22E  [RES0402]  46.2 44.75 270 top
R76  0E  [RES0402]  47.35 44.75 270 top
R77  0E  [RES0402]  49.88 44.75 270 top
R78  0E  [RES0402]  51.15 44.75 270 top
R79  0E  [RES0402]  52.29 44.75 270 top
R80  0E  [RES0402]  53.43 44.75 270 top
R81  0E  [RES0402]  48.62 44.72 270 top
R82  100E  [RES0402]  33.11 42.59 270 top
R83  10K  [RES0402_0-5]  28.42 41.45 270 top
R84  100E  [RES0402]  33.11 40.69 270 top
R85  0E  [RES0402]  25.37 40.18 270 top
R86  0E  [RES0402]  26.51 40.18 270 top
R87  680E  [RES0402]  5.3 40.81 0 bottom
R88  100E  [RES0402]  33.11 38.15 90 top
R89  680E  [RES0402]  5.3 38.78 0 bottom
R90  0E  [RES0402]  11.43 33.32 0 top
R91  0E  [RES0402]  26.64 35.59 270 top
R92  0E  [RES0402]  27.78 35.59 270 top
R93  680E  [RES0402]  5.17 34.21 0 bottom
R94  22E  [RES0402]  30.96 35.35 270 top
R95  22E  [RES0402]  32.1 35.35 270 top
R96  0E  [RES0402]  11.43 32.18 0 top
R97  0E  [RES0402]  9.49 34.19 0 top
R98  0E  [RES0402]  27.27 33.83 180 top
R99  0E  [RES0402]  29.37 35.61 180 top
R100  0E  [RES0402]  9.49 33.05 0 top
R101  0E  [RES0402]  29.3 34.46 180 top
R103  220E  [RES0402_0-5]  91.7 30.16 90 top
R104  10K  [RES0402_0-5]  83.45 30.02 180 top
R107  10K  [RES0402_0-5]  83.45 28.88 180 top
R109  0E  [RES0402]  95.45 27.74 0 top
R111  10K  [RES0402_0-5]  91.32 27.63 180 top
R114  100E  [RES0402]  4.05 25.63 0 top
R115  4.7K  [RES0402]  77.2 25.62 180 top
R117  10K  [RES0402_0-5]  4.05 24.43 180 top
R118  0E  [RES0402]  77.2 24.43 0 top
R120  22E  [RES0402]  27.53 27.48 180 bottom
R121  0E  [RES0402]  77.2 23.29 0 top
R124  0E  [RES0402]  77.2 22.14 0 top
R125  1K  [RES0402]  50.77 22.02 270 top
R126  0E  [RES0402]  52.04 22.02 270 top
R127  0E  [RES0402]  62.07 21.76 180 top
R131  4.7K  [RES0402]  62.07 20.49 180 top
R132  10K  [RES0402_0-5]  81.16 20.49 180 top
R133  4.7K  [RES0402]  84.33 20.16 0 top
R134  4.7K  [RES0402]  87.51 20.04 0 top
R135  4.7K  [RES0402]  89.88 19.99 0 top
R136  0E  [RES0402]  25.1 19.99 180 top
R138  0E  [RES0402]  32.48 19.48 90 top
R139  0E  [RES0402]  33.5 18.72 90 top
R140  0E  [RES0402]  80.91 19.34 0 top
R141  0E  [RES0402]  25.1 18.84 180 top
R142  0E  [RES0402]  27.26 18.34 180 top
R143  0E  [RES0402]  36.97 19.64 180 top
R144  10K  [RES0402_0-5]  41.99 19.63 180 top
R145  4.7K  [RES0402]  80.93 18.23 180 top
R146  0E  [RES0402]  27.26 17.2 180 top
R147  10K  [RES0402_0-5]  41.95 18.48 180 top
R148  0E  [RES0402]  47.21 18.72 270 top
R149  4.7K  [RES0402]  48.35 18.72 270 top
R150  0E  [RES0402]  80.36 14.65 180 top
R151  100E  [RES0402]  3.89 14.2 0 top
R152  0E  [RES0402]  80.36 13.52 180 top
R153  10K  [RES0402_0-5]  3.89 12.99 180 top
R154  220E  [RES0603_0-75]  12.03 12.73 180 top
R155  12K  [RES0603_0-75]  84.82 11.98 270 top
R156  0E  [RES0402]  57.97 8.05 0 top
R157  0E  [RES0402]  60.08 8.05 180 top
R158  4.7K  [RES0402]  57.97 6.9 0 top
R159  100E  [RES0402]  10.07 7.18 90 top
R160  10K  [RES0402_0-5]  12.48 7.18 270 top
R161  100E  [RES0402]  21.81 6.8 90 top
R162  10K  [RES0402_0-5]  23.12 6.8 270 top
R163  220E  [RES0402_0-5]  19.27 91.74 90 bottom
R164  220E  [RES0402_0-5]  17.37 91.74 90 bottom
R165  220E  [RES0402_0-5]  14.19 91.74 90 bottom
R166  220E  [RES0402_0-5]  10.38 91.74 90 bottom
R167  220E  [RES0402_0-5]  12.29 91.74 90 bottom
R168  220E  [RES0402_0-5]  8.48 91.74 90 bottom
R169  220E  [RES0402_0-5]  6.7 91.74 90 bottom
R170  220E  [RES0402_0-5]  4.92 91.74 90 bottom
R171  220E  [RES0402_0-5]  3.02 91.74 90 bottom
R172  10K  [RES0402_0-5]  68.14 75.54 0 bottom
R173  10K  [RES0402_0-5]  13.94 71.67 90 bottom
R174  10K  [RES0402_0-5]  12.67 71.67 90 bottom
R175  10K  [RES0402_0-5]  11.4 71.67 90 bottom
R176  10K  [RES0402_0-5]  10.13 71.67 90 bottom
R177  10K  [RES0402_0-5]  8.86 71.67 90 bottom
R178  10K  [RES0402_0-5]  7.59 71.67 90 bottom
R179  10K  [RES0402_0-5]  6.32 71.67 90 bottom
R180  10K  [RES0402_0-5]  5.05 71.67 90 bottom
R181  2.2K  [RES0402_0-5]  69.44 65.78 180 bottom
R182  22E  [RES0402]  66.22 65.45 0 bottom
R183  2.2K  [RES0402_0-5]  69.44 64.34 180 bottom
R184  6.04K  [RES0402]  58.26 56.31 90 bottom
R185  2.49K  [RES0402]  57.08 56.31 90 bottom
R186  11K  [RES0402_0-5]  55.97 50.97 270 bottom
R187  2.49K  [RES0402]  54.83 50.97 90 bottom
R188  2.49K  [RES0402]  53.69 50.97 90 bottom
R189  11K  [RES0402_0-5]  52.55 50.97 270 bottom
R190  0E  [RES0402]  86.2 45.89 180 bottom
R191  50E  [RES0402]  69.18 45.13 90 bottom
R192  0E  [RES0402]  89.82 44.74 0 bottom
R193  0E  [RES0402]  87.47 44.74 180 bottom
R194  0E  [RES0402]  89.82 43.56 180 bottom
R195  0E  [RES0402]  87.47 43.56 180 bottom
R196  0E  [RES0402]  91.79 43.48 0 bottom
R197  0E  [RES0402]  87.47 42.46 0 bottom
R198  100E  [RES0402]  35.15 42.34 90 bottom
R199  0E  [RES0402]  89.12 41.83 90 bottom
R200  100E  [RES0402]  34 40.94 270 bottom
R201  10K  [RES0402_0-5]  93.69 40.65 270 bottom
R202  10K  [RES0402_0-5]  92.55 40.65 270 bottom
R203  100E  [RES0402]  35.15 39.42 270 bottom
R204  100E  [RES0402]  33.37 38.27 90 bottom
R205  240E  [RES0402]  70.96 38.02 180 bottom
R206  240E  [RES0402]  58.77 38.02 180 bottom
R207  10K  [RES0402_0-5]  97.38 37.18 90 bottom
R208  100E  [RES0402]  35.15 37.13 90 bottom
R209  50E  [RES0402]  74.39 37 0 bottom
R210  50E  [RES0402]  74.39 35.99 0 bottom
R211  10K  [RES0402_0-5]  96.65 35.61 180 bottom
R213  33E  [RES0402_0-5]  33.88 27.61 0 bottom
R214  0E  [RES0402]  40.54 24.05 0 bottom
R215  1K  [RES0402]  30.83 16.07 270 bottom
R216  1K  [RES0402]  29.56 16.07 270 bottom
R217  1K  [RES0402]  28.29 16.07 270 bottom
R218  10K  [RES0402_0-5]  69.35 16.01 180 bottom
R219  10K  [RES0402_0-5]  69.36 14.74 180 bottom
R220  2.2K  [RES0402_0-5]  69 13.05 90 bottom
R221  10K  [RES0402_0-5]  69.44 11.44 180 bottom
R222  10K  [RES0402_0-5]  5.81 81.58 180 bottom
R223  10K  [RES0402_0-5]  5.81 83.49 180 bottom
R224  10K  [RES0402_0-5]  5.81 80.31 180 bottom
RA1  22E  [RESA_EXB28V_0402-4_0-5]  30.83 32.18 90 top
RA2  22E  [RESA_EXB28V_0402-4_0-5]  29.56 29 90 top
RA3  22E  [RESA_EXB28V_0402-4_0-5]  30.7 25.83 90 top
RA4  22E  [RESA_EXB28V_0402-4_0-5]  31.72 22.65 90 top
RA5  51E  [RESA_741C_0402-4_0-5]  79.09 45.13 0 bottom
RA6  51E  [RESA_741C_0402-4_0-5]  76.42 45.13 0 bottom
RA7  51E  [RESA_741C_0402-4_0-5]  73.75 45.13 0 bottom
RA8  51E  [RESA_741C_0402-4_0-5]  71.09 45.13 0 bottom
RA9  51E  [RESA_741C_0402-4_0-5]  82.52 38.78 270 bottom
RA10  51E  [RESA_741C_0402-4_0-5]  82.52 36.11 270 bottom
S1  TDA04H0SB1R  [SW8_50X300_245X245_SMD]  28.92 11.6 0 top
SW1  416131160803  [SW6_4161311608_210X230_SMD_2-7]  10.51 81.58 270 top
SW2  218-8LPSTR  [SW8_218-8LPST_450X230_SMD_2-7]  9.49 67.86 180 top
SW3  500SSP1S2M2QEA  [SW3_500SSP1S2M2_510X260_TH_15-1]  13.64 49.2 180 top
SW4  PTS810 SJG 250 SMTR LFS  [SW4_84X163_170X130_SMD]  4.29 29.64 270 top
SW5  PTS810 SJG 250 SMTR LFS  [SW4_84X163_170X130_SMD]  4.29 18.33 270 top
SW6  PTS810 SJG 250 SMTR LFS  [SW4_84X163_170X130_SMD]  5.29 8.64 0 top
SW7  PTS810 SJG 250 SMTR LFS  [SW4_84X163_170X130_SMD]  17.49 8.3 0 top
TP1  THRU HOLE  [TP_40X80]  80.74 25.62 180 bottom
TP2  THRU HOLE  [TP_40X80]  83.91 25.62 180 bottom
TP3  THRU HOLE  [TP_40X80]  87.09 25.62 180 bottom
TP4  THRU HOLE  [TP_40X80]  90.26 25.62 90 bottom
TP5  THRU HOLE  [TP_40X80]  93.44 25.62 90 bottom
TP6  THRU HOLE  [TP_40X80]  80.74 22.45 180 bottom
TP7  THRU HOLE  [TP_40X80]  83.91 22.45 90 bottom
TP8  THRU HOLE  [TP_40X80]  87.09 22.45 180 bottom
TP9  THRU HOLE  [TP_40X80]  90.26 22.45 180 bottom
TP10  SMD  [TP40_SMD]  84.8 67.61 180 bottom
TP11  SMD  [TP40_SMD]  74.39 51.23 180 bottom
TP12  SMD  [TP40_SMD]  72.23 51.1 180 bottom
TP13  SMD  [TP40_SMD]  65.12 45.64 180 bottom
TP14  SMD  [TP40_SMD]  35.91 22.4 180 bottom
TP15  SMD  [TP40_SMD]  48.48 21.89 180 bottom
TP16  SMD  [TP40_SMD]  46.2 21.89 180 bottom
TP17  SMD  [TP40_SMD]  43.91 21.89 180 bottom
TP18  SMD  [TP40_SMD]  47.34 20.11 180 bottom
TP19  SMD  [TP40_SMD]  45.05 20.11 180 bottom
TP20  SMD  [TP40_SMD]  42.83 20.11 180 bottom
TP21  SMD  [TP40_SMD]  40.86 20.11 180 bottom
TP22  SMD  [TP40_SMD]  38.83 19.99 180 bottom
TP23  SMD  [TP40_SMD]  36.86 19.99 180 bottom
TP27  SMD  [TP40_SMD]  8.98 40.94 180 bottom
TP28  SMD  [TP40_SMD]  8.86 38.53 180 bottom
TP29  SMD  [TP40_SMD]  34.89 19.99 180 bottom
TP30  SMD  [TP40_SMD]  95.34 20.62 180 bottom
TP31  SMD  [TP40_SMD]  94.33 70.53 180 bottom
TP32  THRU HOLE  [TP_40X80]  9.62 15.79 0 top
TP33  THRU HOLE  [TP_40X80]  22.7 92.63 0 top
U1  LM26400YMHX  [ETSSOP16_25-59_200X180]  28.67 85.48 270 top
U2  LM26400YMHX  [ETSSOP16_25-59_200X180]  53.43 85.48 270 top
U3  FT4232HL  [LQFP64_19-68_390X390]  78.45 83.7 180 top
U4  93LC56C-I/SN  [SOIC8_1-8]  88.09 71.61 0 top
U5  TPS7A8101DRBT  [SON8_25-59_120X120]  51.61 63.55 90 top
U6  DP83867IRPAPT  [EQFP64_19-68_400X400]  65.88 59.82 180 top
U7  AT24CM02  [SOIC8]  32.48 56.05 0 top
U8  100.000MHz  [OSC6_ASEMP_130X100_SMD_0-9]  36.2 48.18 180 top
U9  100.000MHz  [OSC6_ASEMP_130X100_SMD_0-9]  30.32 38.27 270 top
U10  MT41K1G8SN-125 IT:A  [FBGA78_31-49_360X520_1-2]  63.09 36.88 180 top
U11  MT41K1G8SN-125 IT:A  [FBGA78_31-49_360X520_1-2]  74.9 36.88 180 top
U12  LFE5UM-85F-8BG381I  [CABGA381_31-49_670X670_1-8]  43.4 33.91 0 top
U13  SN74LVC1G08DRLR  [SOT553-5_0-6]  39.46 19.14 180 top
U14  MT25QL128ABA8ESF-0SIT  [SOIC16_W_2-7]  55.21 14.77 90 top
U15  FT2232HL  [LQFP64_19-68_400X400]  71.72 14.24 180 top
U16  TPD6E001RSER  [UQFN10_19-68_80X60_0-6]  72.36 73.45 270 bottom
U17  TPD4E05U06QDQARQ1  [USON10_TPD4E05U_40X100_0-6]  78.58 58.72 180 bottom
U18  TPD4E05U06QDQARQ1  [USON10_TPD4E05U_40X100_0-6]  78.58 55.04 180 bottom
U19  TPS51200DRCT  [SON10_19-68_125X125_1]  93.31 37.34 90 bottom
U20  93LC56C-I/SN  [SOIC8_1-8]  64.48 14.1 180 bottom
Y1  12.000MHz  [XTAL4_86-61X62-99_130X105_SMD_0-6]  89.63 76.75 90 top
Y2  25.000MHz  [XTAL_ABM3_205X130_SMD_1-4]  76.04 68.37 270 top
Y3  12.000MHz  [XTAL4_86-61X62-99_130X105_SMD_0-6]  83.79 8.3 90 top

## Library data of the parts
C1-C125 C127-C216 = CAP
C126 = CAP_POL
D1-D8 = DIODE_SCHOTTKY
D9 D11 = TPD2EUSB30D_SOT-3
D10 D12-D14 = DIODE_SOD323
D15 = DIODE_PESD
D16 = DIODE_TVS_DUAL
F1 = FUSE
FB1-FB4 = INDUCTOR_FERRITE
FL1-FL10 = EMIFILTER_IND
J1 J4 = CON_USB-B_5_4SH
J2 = CON_PWRJACK3_RAPC722
J3 = CON_PMC_30X2_M
J5 = CON_SDCARD_8_DM3AT-SF-PEJM
J6 = CON_RJ45-14_LPJG16414A4NL
L1-L4 = INDUCTOR
LD1-LD15 = DIODE_LED
Q1 = NPN_BEC
R1-R22 R25-R34 R37-R46 R49 R50 R53 R54 R57 R63 R64 R67-R71 R73 R75 R76 R81-R84 R86-R90 R92 R93 R97-R100 R103 R104 R107 R109 R111 R114 R115 R117 R118 R121 R124-R127 R131-R136 R138-R149 R151 R153-R180 R182 R184 R190-R211 R213-R219 R221-R224 = RESISTOR
R23 R24 R48 R60-R62 R77-R80 R85 R91 R96 R101 R150 R152 = RESISTOR: signal model: RESISTOR_RES0402_0-5_0E_0E
R35 R51 R52 R55 R56 R58 R59 R65 R66 R181 R183 R185-R189 R220 = RESISTOR: room: PHY_6
R47 R72 R74 R94 R95 R120 = RESISTOR: signal model: RESISTOR_RES0402_22E_1%_22E_1%
RA1-RA4 = RESARR_ISO4: signal model: RESARR_ISO4_RESA_EXB28V_0402-4__22E
RA5-RA10 = RESARR_ISO4
S1 = SW8_TDA04H0SB1R
SW1 = SW6_219-3MST
SW2 = SW8_218-8LPSTR
SW3 = SW3_1103
SW4-SW7 = SW4_1571634
TP1-TP23 TP27-TP33 = TESTPOINT
U1 U2 = LM26400YMHX_HTSSOP16
U3 = FT4232H _LQFP64
U4 U20 = 93LC56B-I/SN_SOIC8
U5 = TPS7A8101DRB_SON8
U6 = DP83867IRPAPT_HTQFP64
U7 = AT24CM02-SSHD_SOIC8
U8 U9 = OSC6_ASEMPXX
U10 U11 = MT41J128M8JP-125_FBGA78
U12 = LFE5UM-85F-7BG381I_CSBGA381
U13 = SN74LVC1G08DRLR_SOT553-5
U14 = MT25QL128ABA8ESF_SOIC16
U15 = FT2232H_LQFP64
U16 = TPD6E001RSE_UQFN10
U17 U18 = TPD4E05U06DQAR_USON10
U19 = TPS51200DRCT_SON10
Y1 Y3 = CRY4_13
Y2 = CRY

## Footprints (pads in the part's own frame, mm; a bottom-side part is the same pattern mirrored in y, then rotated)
CABGA381_31-49_670X670_1-8
  round 0.356 smd: A2(-6.8,7.6) A3(-6,7.6) A4(-5.2,7.6) A5(-4.4,7.6) A6(-3.6,7.6) A7(-2.8,7.6) A8(-2,7.6) A9(-1.2,7.6) A10(-0.4,7.6) A11(0.4,7.6) A12(1.2,7.6) A13(2,7.6) A14(2.8,7.6) A15(3.6,7.6) A16(4.4,7.6) A17(5.2,7.6) A18(6,7.6) A19(6.8,7.6) B1(-7.6,6.8) B2(-6.8,6.8) B3(-6,6.8) B4(-5.2,6.8) B5(-4.4,6.8) B6(-3.6,6.8) B7(-2.8,6.8) B8(-2,6.8) B9(-1.2,6.8) B10(-0.4,6.8) B11(0.4,6.8) B12(1.2,6.8) B13(2,6.8) B14(2.8,6.8) B15(3.6,6.8) B16(4.4,6.8) B17(5.2,6.8) B18(6,6.8) B19(6.8,6.8) B20(7.6,6.8) C1(-7.6,6) C2(-6.8,6) C3(-6,6) C4(-5.2,6) C5(-4.4,6) C6(-3.6,6) C7(-2.8,6) C8(-2,6) C9(-1.2,6) C10(-0.4,6) C11(0.4,6) C12(1.2,6) C13(2,6) C14(2.8,6) C15(3.6,6) C16(4.4,6) C17(5.2,6) C18(6,6) C19(6.8,6) C20(7.6,6) D1(-7.6,5.2) D2(-6.8,5.2) D3(-6,5.2) D4(-5.2,5.2) D5(-4.4,5.2) D6(-3.6,5.2) D7(-2.8,5.2) D8(-2,5.2) D9(-1.2,5.2) D10(-0.4,5.2) D11(0.4,5.2) D12(1.2,5.2) D13(2,5.2) D14(2.8,5.2) D15(3.6,5.2) D16(4.4,5.2) D17(5.2,5.2) D18(6,5.2) D19(6.8,5.2) D20(7.6,5.2) E1(-7.6,4.4) E2(-6.8,4.4) E3(-6,4.4) E4(-5.2,4.4) E5(-4.4,4.4) E6(-3.6,4.4) E7(-2.8,4.4) E8(-2,4.4) E9(-1.2,4.4) E10(-0.4,4.4) E11(0.4,4.4) E12(1.2,4.4) E13(2,4.4) E14(2.8,4.4) E15(3.6,4.4) E16(4.4,4.4) E17(5.2,4.4) E18(6,4.4) E19(6.8,4.4) E20(7.6,4.4) F1(-7.6,3.6) F2(-6.8,3.6) F3(-6,3.6) F4(-5.2,3.6) F5(-4.4,3.6) F6(-3.6,3.6) F7(-2.8,3.6) F8(-2,3.6) F9(-1.2,3.6) F10(-0.4,3.6) F11(0.4,3.6) F12(1.2,3.6) F13(2,3.6) F14(2.8,3.6) F15(3.6,3.6) F16(4.4,3.6) F17(5.2,3.6) F18(6,3.6) F19(6.8,3.6) F20(7.6,3.6) G1(-7.6,2.8) G2(-6.8,2.8) G3(-6,2.8) G4(-5.2,2.8) G5(-4.4,2.8) G6(-3.6,2.8) G7(-2.8,2.8) G8(-2,2.8) G9(-1.2,2.8) G10(-0.4,2.8) G11(0.4,2.8) G12(1.2,2.8) G13(2,2.8) G14(2.8,2.8) G15(3.6,2.8) G16(4.4,2.8) G17(5.2,2.8) G18(6,2.8) G19(6.8,2.8) G20(7.6,2.8) H1(-7.6,2) H2(-6.8,2) H3(-6,2) H4(-5.2,2) H5(-4.4,2) H6(-3.6,2) H7(-2.8,2) H8(-2,2) H9(-1.2,2) H10(-0.4,2) H11(0.4,2) H12(1.2,2) H13(2,2) H14(2.8,2) H15(3.6,2) H16(4.4,2) H17(5.2,2) H18(6,2) H19(6.8,2) H20(7.6,2) J1(-7.6,1.2) J2(-6.8,1.2) J3(-6,1.2) J4(-5.2,1.2) J5(-4.4,1.2) J6(-3.6,1.2) J7(-2.8,1.2) J8(-2,1.2) J9(-1.2,1.2) J10(-0.4,1.2) J11(0.4,1.2) J12(1.2,1.2) J13(2,1.2) J14(2.8,1.2) J15(3.6,1.2) J16(4.4,1.2) J17(5.2,1.2) J18(6,1.2) J19(6.8,1.2) J20(7.6,1.2) K1(-7.6,0.4) K2(-6.8,0.4) K3(-6,0.4) K4(-5.2,0.4) K5(-4.4,0.4) K6(-3.6,0.4) K7(-2.8,0.4) K8(-2,0.4) K9(-1.2,0.4) K10(-0.4,0.4) K11(0.4,0.4) K12(1.2,0.4) K13(2,0.4) K14(2.8,0.4) K15(3.6,0.4) K16(4.4,0.4) K17(5.2,0.4) K18(6,0.4) K19(6.8,0.4) K20(7.6,0.4) L1(-7.6,-0.4) L2(-6.8,-0.4) L3(-6,-0.4) L4(-5.2,-0.4) L5(-4.4,-0.4) L6(-3.6,-0.4) L7(-2.8,-0.4) L8(-2,-0.4) L9(-1.2,-0.4) L10(-0.4,-0.4) L11(0.4,-0.4) L12(1.2,-0.4) L13(2,-0.4) L14(2.8,-0.4) L15(3.6,-0.4) L16(4.4,-0.4) L17(5.2,-0.4) L18(6,-0.4) L19(6.8,-0.4) L20(7.6,-0.4) M1(-7.6,-1.2) M2(-6.8,-1.2) M3(-6,-1.2) M4(-5.2,-1.2) M5(-4.4,-1.2) M6(-3.6,-1.2) M7(-2.8,-1.2) M8(-2,-1.2) M9(-1.2,-1.2) M10(-0.4,-1.2) M11(0.4,-1.2) M12(1.2,-1.2) M13(2,-1.2) M14(2.8,-1.2) M15(3.6,-1.2) M16(4.4,-1.2) M17(5.2,-1.2) M18(6,-1.2) M19(6.8,-1.2) M20(7.6,-1.2) N1(-7.6,-2) N2(-6.8,-2) N3(-6,-2) N4(-5.2,-2) N5(-4.4,-2) N6(-3.6,-2) N7(-2.8,-2) N8(-2,-2) N9(-1.2,-2) N10(-0.4,-2) N11(0.4,-2) N12(1.2,-2) N13(2,-2) N14(2.8,-2) N15(3.6,-2) N16(4.4,-2) N17(5.2,-2) N18(6,-2) N19(6.8,-2) N20(7.6,-2) P1(-7.6,-2.8) P2(-6.8,-2.8) P3(-6,-2.8) P4(-5.2,-2.8) P5(-4.4,-2.8) P6(-3.6,-2.8) P7(-2.8,-2.8) P8(-2,-2.8) P9(-1.2,-2.8) P10(-0.4,-2.8) P11(0.4,-2.8) P12(1.2,-2.8) P13(2,-2.8) P14(2.8,-2.8) P15(3.6,-2.8) P16(4.4,-2.8) P17(5.2,-2.8) P18(6,-2.8) P19(6.8,-2.8) P20(7.6,-2.8) R1(-7.6,-3.6) R2(-6.8,-3.6) R3(-6,-3.6) R4(-5.2,-3.6) R5(-4.4,-3.6) R16(4.4,-3.6) R17(5.2,-3.6) R18(6,-3.6) R19(6.8,-3.6) R20(7.6,-3.6) T1(-7.6,-4.4) T2(-6.8,-4.4) T3(-6,-4.4) T4(-5.2,-4.4) T5(-4.4,-4.4) T6(-3.6,-4.4) T7(-2.8,-4.4) T8(-2,-4.4) T9(-1.2,-4.4) T10(-0.4,-4.4) T11(0.4,-4.4) T12(1.2,-4.4) T13(2,-4.4) T14(2.8,-4.4) T15(3.6,-4.4) T16(4.4,-4.4) T17(5.2,-4.4) T18(6,-4.4) T19(6.8,-4.4) T20(7.6,-4.4) U1(-7.6,-5.2) U2(-6.8,-5.2) U3(-6,-5.2) U4(-5.2,-5.2) U5(-4.4,-5.2) U6(-3.6,-5.2) U7(-2.8,-5.2) U8(-2,-5.2) U9(-1.2,-5.2) U10(-0.4,-5.2) U11(0.4,-5.2) U12(1.2,-5.2) U13(2,-5.2) U14(2.8,-5.2) U15(3.6,-5.2) U16(4.4,-5.2) U17(5.2,-5.2) U18(6,-5.2) U19(6.8,-5.2) U20(7.6,-5.2) V1(-7.6,-6) V2(-6.8,-6) V3(-6,-6) V4(-5.2,-6) V5(-4.4,-6) V6(-3.6,-6) V7(-2.8,-6) V8(-2,-6) V9(-1.2,-6) V10(-0.4,-6) V11(0.4,-6) V12(1.2,-6) V13(2,-6) V14(2.8,-6) V15(3.6,-6) V16(4.4,-6) V17(5.2,-6) V18(6,-6) V19(6.8,-6) V20(7.6,-6) W1(-7.6,-6.8) W2(-6.8,-6.8) W3(-6,-6.8) W4(-5.2,-6.8) W5(-4.4,-6.8) W6(-3.6,-6.8) W7(-2.8,-6.8) W8(-2,-6.8) W9(-1.2,-6.8) W10(-0.4,-6.8) W11(0.4,-6.8) W12(1.2,-6.8) W13(2,-6.8) W14(2.8,-6.8) W15(3.6,-6.8) W16(4.4,-6.8) W17(5.2,-6.8) W18(6,-6.8) W19(6.8,-6.8) W20(7.6,-6.8) Y2(-6.8,-7.6) Y3(-6,-7.6) Y5(-4.4,-7.6) Y6(-3.6,-7.6) Y7(-2.8,-7.6) Y8(-2,-7.6) Y11(0.4,-7.6) Y12(1.2,-7.6) Y14(2.8,-7.6) Y15(3.6,-7.6) Y16(4.4,-7.6) Y17(5.2,-7.6) Y19(6.8,-7.6)
CAP0201
  rect 0.356x0.33 smd: 1(-0.28,0) 2(0.28,0)
CAP0201_0-5
  rect 0.356x0.33 smd: 1(-0.28,0) 2(0.28,0)
CAP0402
  rect 0.483x0.584 smd: 1(-0.46,0) 2(0.46,0)
CAP0402_0-75
  rect 0.483x0.584 smd: 1(-0.46,0) 2(0.46,0)
CAP0603_1
  rect 0.711x0.889 smd: 1(-0.7,0) 2(0.7,0)
CAP0805_1-5
  rect 0.94x1.346 smd: 1(-0.8,0) 2(0.8,0)
CAP1206
  rect 0.991x1.702 smd: 1(-1.35,0) 2(1.35,0)
CAP1210
  rect 0.965x2.718 smd: 1(-1.65,0) 2(1.65,0)
CAPT7343D_3-25
  rect 2.362x2.438 smd: 1(-3.1,0) 2(3.1,0)
CON_PMC2X30_QTH-30_P_S_S_4-3
  round 0.889 hole 1.016 unplated: (-9.24,2.04) (9.24,2.04)
  rect 0.305x1.448 smd: 1(-7.25,3.09) 2(-7.25,-3.08) 3(-6.75,3.09) 4(-6.75,-3.08) 5(-6.25,3.09) 6(-6.25,-3.08) 7(-5.75,3.09) 8(-5.75,-3.08) 9(-5.25,3.09) 10(-5.25,-3.08) 11(-4.75,3.09) 12(-4.75,-3.08) 13(-4.25,3.09) 14(-4.25,-3.08) 15(-3.75,3.09) 16(-3.75,-3.08) 17(-3.25,3.09) 18(-3.25,-3.08) 19(-2.75,3.09) 20(-2.75,-3.08) 21(-2.25,3.09) 22(-2.25,-3.08) 23(-1.75,3.09) 24(-1.75,-3.08) 25(-1.25,3.09) 26(-1.25,-3.08) 27(-0.75,3.09) 28(-0.75,-3.08) 29(-0.25,3.09) 30(-0.25,-3.08) 31(0.25,3.09) 32(0.25,-3.08) 33(0.75,3.09) 34(0.75,-3.08) 35(1.25,3.09) 36(1.25,-3.08) 37(1.75,3.09) 38(1.75,-3.08) 39(2.25,3.09) 40(2.25,-3.08) 41(2.75,3.09) 42(2.75,-3.08) 43(3.25,3.09) 44(3.25,-3.08) 45(3.75,3.09) 46(3.75,-3.08) 47(4.25,3.09) 48(4.25,-3.08) 49(4.75,3.09) 50(4.75,-3.08) 51(5.25,3.09) 52(5.25,-3.08) 53(5.75,3.09) 54(5.75,-3.08) 55(6.25,3.09) 56(6.25,-3.08) 57(6.75,3.09) 58(6.75,-3.08) 59(7.25,3.09) 60(7.25,-3.08)
  rect 2.54x0.635 smd: 61(-8.445,0.01) 64(8.445,0.01)
  rect 4.699x0.635 smd: 62(-3.175,0.01) 63(3.175,0.01)
CON_PWRJACK3_RAPC722_P_R_T
  rect 4.826x2.032 hole 3.556x1.016: 1(0,0.024)
  rect 4.064x1.778 hole 3.048x0.762: 2(0,-6.226)
  rect 1.778x4.064 hole 0.762x3.048: 3(4.8,-2.976)
CON_RJ45-14_LPJG16414A4NL_S_R_T_13-5
  round 3.124 hole 3.251 unplated: (0,-8.89) (11.43,-8.89)
  rect 1.6x1.6 hole 0.914: 1(0,0)
  round 1.6 hole 0.914: 2(1.27,-2.54) 3(2.54,0) 4(3.81,-2.54) 5(5.08,0) 6(6.35,-2.54) 7(7.62,0) 8(8.89,-2.54) 9(10.16,0) 10(11.43,-2.54)
  round 1.702 hole 1.016: 11(12.44,-11.43) 12(12.44,-13.46) 13(-1.01,-11.43) 14(-1.01,-13.46)
  round 2.362 hole 1.676: SH1(-2.16,-5.84) SH2(13.59,-5.84)
CON_SD8_DM3AT-SF_S_R_S_1-7
  rect 0.711x1.219 smd: 1(3.3,7.33) 2(2.2,7.33) 3(1.1,7.33) 4(0,7.33) 5(-1.1,7.33) 6(-2.2,7.33) 7(-3.3,7.33) 8(-4.4,7.33) 9(-5.35,7.33)
  rect 1.016x1.219 smd: 10(4.85,7.33) 11(-6.3,3.03)
  rect 1.016x0.813 smd: 12(-6.3,-3.17)
  rect 1.016x2.819 smd: 13(-6.3,-7.32)
  rect 1.321x1.905 smd: 14(7.2,-7.77)
CON_USBB5_105017-01_S_R_S_2-6
  rect 1.499x1.905 smd: (-1,-0.517) (1,-0.517)
  rect 0.406x1.346 smd: 1(-1.3,2.183) 2(-0.65,2.183) 3(0,2.183) 4(0.65,2.183) 5(1.3,2.183)
  round 1.448 hole 0.864: SH1(-2.5,2.183) SH2(2.5,2.183)
  custom 0.45x0.45 hole 0.61x1.321: SH3(-3.5,-0.517) SH4(3.5,-0.517)
DIO_DFN0402
  rect 0.508x0.66 smd: 1(-0.42,0) 2(0.42,0)
DIO_POWERDI-323_0-7
  rect 1.118x2.007 smd: 1(0,0.95)
  rect 0.813x0.813 smd: 2(0,-0.95)
DIO_SMC
  rect 2.21x3.099 smd: 1(-3.5,0) 2(3.5,0)
DIO_SOD323
  rect 0.762x0.457 smd: 1(-1.2,0) 2(1.2,0)
EMIFIL_BLM21P_0805_1-1
  rect 1.168x1.473 smd: 1(-0.9,0) 2(0.9,0)
EQFP64_19-68_400X400
  rect 1.499x0.305 smd: 1(-5.7,3.75) 2(-5.7,3.25) 3(-5.7,2.75) 4(-5.7,2.25) 5(-5.7,1.75) 6(-5.7,1.25) 7(-5.7,0.75) 8(-5.7,0.25) 9(-5.7,-0.25) 10(-5.7,-0.75) 11(-5.7,-1.25) 12(-5.7,-1.75) 13(-5.7,-2.25) 14(-5.7,-2.75) 15(-5.7,-3.25) 16(-5.7,-3.75) 33(5.7,-3.75) 34(5.7,-3.25) 35(5.7,-2.75) 36(5.7,-2.25) 37(5.7,-1.75) 38(5.7,-1.25) 39(5.7,-0.75) 40(5.7,-0.25) 41(5.7,0.25) 42(5.7,0.75) 43(5.7,1.25) 44(5.7,1.75) 45(5.7,2.25) 46(5.7,2.75) 47(5.7,3.25) 48(5.7,3.75)
  rect 0.305x1.499 smd: 17(-3.75,-5.7) 18(-3.25,-5.7) 19(-2.75,-5.7) 20(-2.25,-5.7) 21(-1.75,-5.7) 22(-1.25,-5.7) 23(-0.75,-5.7) 24(-0.25,-5.7) 25(0.25,-5.7) 26(0.75,-5.7) 27(1.25,-5.7) 28(1.75,-5.7) 29(2.25,-5.7) 30(2.75,-5.7) 31(3.25,-5.7) 32(3.75,-5.7) 49(3.75,5.7) 50(3.25,5.7) 51(2.75,5.7) 52(2.25,5.7) 53(1.75,5.7) 54(1.25,5.7) 55(0.75,5.7) 56(0.25,5.7) 57(-0.25,5.7) 58(-0.75,5.7) 59(-1.25,5.7) 60(-1.75,5.7) 61(-2.25,5.7) 62(-2.75,5.7) 63(-3.25,5.7) 64(-3.75,5.7)
  rect 4.42x4.42 smd: 65(0,0)
ETSSOP16_25-59_200X180
  rect 1.473x0.457 smd: 1(-2.9,2.275) 2(-2.9,1.625) 3(-2.9,0.975) 4(-2.9,0.325) 5(-2.9,-0.325) 6(-2.9,-0.975) 7(-2.9,-1.625) 8(-2.9,-2.275) 9(2.9,-2.275) 10(2.9,-1.625) 11(2.9,-0.975) 12(2.9,-0.325) 13(2.9,0.325) 14(2.9,0.975) 15(2.9,1.625) 16(2.9,2.275)
  rect 2.997x2.997 smd: 17(0,0)
FBGA78_31-49_360X520_1-2
  round 0.457 smd: A1(-3.2,4.8) A2(-2.4,4.8) A3(-1.6,4.8) A7(1.6,4.8) A8(2.4,4.8) A9(3.2,4.8) B1(-3.2,4) B2(-2.4,4) B3(-1.6,4) B7(1.6,4) B8(2.4,4) B9(3.2,4) C1(-3.2,3.2) C2(-2.4,3.2) C3(-1.6,3.2) C7(1.6,3.2) C8(2.4,3.2) C9(3.2,3.2) D1(-3.2,2.4) D2(-2.4,2.4) D3(-1.6,2.4) D7(1.6,2.4) D8(2.4,2.4) D9(3.2,2.4) E1(-3.2,1.6) E2(-2.4,1.6) E3(-1.6,1.6) E7(1.6,1.6) E8(2.4,1.6) E9(3.2,1.6) F1(-3.2,0.8) F2(-2.4,0.8) F3(-1.6,0.8) F7(1.6,0.8) F8(2.4,0.8) F9(3.2,0.8) G1(-3.2,0) G2(-2.4,0) G3(-1.6,0) G7(1.6,0) G8(2.4,0) G9(3.2,0) H1(-3.2,-0.8) H2(-2.4,-0.8) H3(-1.6,-0.8) H7(1.6,-0.8) H8(2.4,-0.8) H9(3.2,-0.8) J1(-3.2,-1.6) J2(-2.4,-1.6) J3(-1.6,-1.6) J7(1.6,-1.6) J8(2.4,-1.6) J9(3.2,-1.6) K1(-3.2,-2.4) K2(-2.4,-2.4) K3(-1.6,-2.4) K7(1.6,-2.4) K8(2.4,-2.4) K9(3.2,-2.4) L1(-3.2,-3.2) L2(-2.4,-3.2) L3(-1.6,-3.2) L7(1.6,-3.2) L8(2.4,-3.2) L9(3.2,-3.2) M1(-3.2,-4) M2(-2.4,-4) M3(-1.6,-4) M7(1.6,-4) M8(2.4,-4) M9(3.2,-4) N1(-3.2,-4.8) N2(-2.4,-4.8) N3(-1.6,-4.8) N7(1.6,-4.8) N8(2.4,-4.8) N9(3.2,-4.8)
FUSE_1206
  rect 1.194x1.702 smd: 1(-1.55,0) 2(1.55,0)
IND0402
  rect 0.61x0.61 smd: 1(-0.46,0) 2(0.46,0)
IND_IHLP2020CZ_230X215_SMD
  rect 1.905x2.794 smd: 1(-2.037,0) 2(2.037,0)
IND_NRS5020_200X200_SMD_3-1
  rect 4.013x1.524 smd: 1(0,-1.8) 2(0,1.8)
LED_0603
  rect 0.762x0.838 smd: 1(-0.7,0) 2(0.7,0)
LED_0603_0-8
  rect 0.762x0.838 smd: 1(-0.7,0) 2(0.7,0)
LQFP64_19-68_390X390
  rect 1.194x0.254 smd: 1(-5.65,3.75) 2(-5.65,3.25) 3(-5.65,2.75) 4(-5.65,2.25) 5(-5.65,1.75) 6(-5.65,1.25) 7(-5.65,0.75) 8(-5.65,0.25) 9(-5.65,-0.25) 10(-5.65,-0.75) 11(-5.65,-1.25) 12(-5.65,-1.75) 13(-5.65,-2.25) 14(-5.65,-2.75) 15(-5.65,-3.25) 16(-5.65,-3.75) 33(5.65,-3.75) 34(5.65,-3.25) 35(5.65,-2.75) 36(5.65,-2.25) 37(5.65,-1.75) 38(5.65,-1.25) 39(5.65,-0.75) 40(5.65,-0.25) 41(5.65,0.25) 42(5.65,0.75) 43(5.65,1.25) 44(5.65,1.75) 45(5.65,2.25) 46(5.65,2.75) 47(5.65,3.25) 48(5.65,3.75)
  rect 0.254x1.194 smd: 17(-3.75,-5.65) 18(-3.25,-5.65) 19(-2.75,-5.65) 20(-2.25,-5.65) 21(-1.75,-5.65) 22(-1.25,-5.65) 23(-0.75,-5.65) 24(-0.25,-5.65) 25(0.25,-5.65) 26(0.75,-5.65) 27(1.25,-5.65) 28(1.75,-5.65) 29(2.25,-5.65) 30(2.75,-5.65) 31(3.25,-5.65) 32(3.75,-5.65) 49(3.75,5.65) 50(3.25,5.65) 51(2.75,5.65) 52(2.25,5.65) 53(1.75,5.65) 54(1.25,5.65) 55(0.75,5.65) 56(0.25,5.65) 57(-0.25,5.65) 58(-0.75,5.65) 59(-1.25,5.65) 60(-1.75,5.65) 61(-2.25,5.65) 62(-2.75,5.65) 63(-3.25,5.65) 64(-3.75,5.65)
LQFP64_19-68_400X400
  rect 1.524x0.305 smd: 1(-5.7,3.75) 2(-5.7,3.25) 3(-5.7,2.75) 4(-5.7,2.25) 5(-5.7,1.75) 6(-5.7,1.25) 7(-5.7,0.75) 8(-5.7,0.25) 9(-5.7,-0.25) 10(-5.7,-0.75) 11(-5.7,-1.25) 12(-5.7,-1.75) 13(-5.7,-2.25) 14(-5.7,-2.75) 15(-5.7,-3.25) 16(-5.7,-3.75) 33(5.7,-3.75) 34(5.7,-3.25) 35(5.7,-2.75) 36(5.7,-2.25) 37(5.7,-1.75) 38(5.7,-1.25) 39(5.7,-0.75) 40(5.7,-0.25) 41(5.7,0.25) 42(5.7,0.75) 43(5.7,1.25) 44(5.7,1.75) 45(5.7,2.25) 46(5.7,2.75) 47(5.7,3.25) 48(5.7,3.75)
  rect 0.305x1.524 smd: 17(-3.75,-5.7) 18(-3.25,-5.7) 19(-2.75,-5.7) 20(-2.25,-5.7) 21(-1.75,-5.7) 22(-1.25,-5.7) 23(-0.75,-5.7) 24(-0.25,-5.7) 25(0.25,-5.7) 26(0.75,-5.7) 27(1.25,-5.7) 28(1.75,-5.7) 29(2.25,-5.7) 30(2.75,-5.7) 31(3.25,-5.7) 32(3.75,-5.7) 49(3.75,5.7) 50(3.25,5.7) 51(2.75,5.7) 52(2.25,5.7) 53(1.75,5.7) 54(1.25,5.7) 55(0.75,5.7) 56(0.25,5.7) 57(-0.25,5.7) 58(-0.75,5.7) 59(-1.25,5.7) 60(-1.75,5.7) 61(-2.25,5.7) 62(-2.75,5.7) 63(-3.25,5.7) 64(-3.75,5.7)
OSC6_ASEMP_130X100_SMD_0-9
  rect 0.914x1.016 smd: 1(-1.05,-0.95) 3(1.05,-0.95) 4(1.05,0.95) 6(-1.05,0.95)
  rect 0.508x1.016 smd: 2(0,-0.95) 5(0,0.95)
RES0402
  rect 0.483x0.508 smd: 1(-0.42,0) 2(0.42,0)
RES0402_0-5
  rect 0.483x0.508 smd: 1(-0.42,0) 2(0.42,0)
RES0603_0-75
  rect 0.711x0.889 smd: 1(-0.7,0) 2(0.7,0)
RES0805
  rect 0.762x1.346 smd: 1(-0.9,0) 2(0.9,0)
RESA_741C_0402-4_0-5
  rect 0.279x0.508 smd: 1(-0.75,-0.5) 2(-0.25,-0.5) 3(0.25,-0.5) 4(0.75,-0.5) 5(0.75,0.5) 6(0.25,0.5) 7(-0.25,0.5) 8(-0.75,0.5)
RESA_EXB28V_0402-4_0-5
  rect 0.533x0.508 smd: 1(-0.887,-0.45) 4(0.887,-0.45) 5(0.887,0.45) 8(-0.887,0.45)
  rect 0.254x0.508 smd: 2(-0.25,-0.45) 3(0.25,-0.45) 6(0.25,0.45) 7(-0.25,0.45)
SOIC8
  rect 1.346x0.559 smd: 1(-2.6,1.905) 2(-2.6,0.635) 3(-2.6,-0.635) 4(-2.6,-1.905) 5(2.6,-1.905) 6(2.6,-0.635) 7(2.6,0.635) 8(2.6,1.905)
SOIC8_1-8
  rect 1.346x0.559 smd: 1(-2.6,1.905) 2(-2.6,0.635) 3(-2.6,-0.635) 4(-2.6,-1.905) 5(2.6,-1.905) 6(2.6,-0.635) 7(2.6,0.635) 8(2.6,1.905)
SOIC16_W_2-7
  rect 2.007x0.61 smd: 1(-4.65,4.445) 2(-4.65,3.175) 3(-4.65,1.905) 4(-4.65,0.635) 5(-4.65,-0.635) 6(-4.65,-1.905) 7(-4.65,-3.175) 8(-4.65,-4.445) 9(4.65,-4.445) 10(4.65,-3.175) 11(4.65,-1.905) 12(4.65,-0.635) 13(4.65,0.635) 14(4.65,1.905) 15(4.65,3.175) 16(4.65,4.445)
SON8_25-59_120X120
  rect 0.838x0.356 smd: 1(-1.475,0.975) 2(-1.475,0.325) 3(-1.475,-0.325) 4(-1.475,-0.975) 5(1.475,-0.975) 6(1.475,-0.325) 7(1.475,0.325) 8(1.475,0.975)
  custom 0.375x0.375 smd: 9(0,0)
SON10_19-68_125X125_1
  rect 0.838x0.279 smd: 1(-1.475,1) 2(-1.475,0.5) 3(-1.475,0) 4(-1.475,-0.5) 5(-1.475,-1) 6(1.475,-1) 7(1.475,-0.5) 8(1.475,0) 9(1.475,0.5) 10(1.475,1)
  custom 0.412x0.412 smd: 11(0,0)
SOT553-5_0-6
  rect 0.66x0.254 smd: 1(-0.74,0.5) 2(-0.74,0) 3(-0.74,-0.5) 4(0.74,-0.5) 5(0.74,0.5)
SOT-3
  rect 0.381x0.152 smd: 1(-0.47,0.35) 2(-0.47,-0.35) 3(0.47,0)
SW3_500SSP1S2M2_510X260_TH_15-1
  rect 2.515x2.515 hole 1.829: 1(0,0)
  round 2.515 hole 1.829: 2(4.7,0) 3(9.4,0)
SW4_84X163_170X130_SMD
  rect 1.067x0.66 smd: 1(-2.075,1.075) 2(2.075,1.075) 3(-2.075,-1.075) 4(2.075,-1.075)
SW6_4161311608_210X230_SMD_2-7
  rect 0.762x1.27 smd: 1(-1.27,-3.81) 2(0,-3.81) 3(1.27,-3.81) 4(1.27,3.81) 5(0,3.81) 6(-1.27,3.81)
SW8_50X300_245X245_SMD
  rect 0.762x1.27 smd: 1(-1.905,-3.81) 2(-0.635,-3.81) 3(0.635,-3.81) 4(1.905,-3.81) 5(1.905,3.81) 6(0.635,3.81) 7(-0.635,3.81) 8(-1.905,3.81)
SW8_218-8LPST_450X230_SMD_2-7
  rect 0.762x1.27 smd: 1(-4.445,-3.81) 2(-3.175,-3.81) 3(-1.905,-3.81) 4(-0.635,-3.81) 5(0.635,-3.81) 6(1.905,-3.81) 7(3.175,-3.81) 8(4.445,-3.81) 9(4.445,3.81) 10(3.175,3.81) 11(1.905,3.81) 12(0.635,3.81) 13(-0.635,3.81) 14(-1.905,3.81) 15(-3.175,3.81) 16(-4.445,3.81)
TO_SOT23-123
  rect 1.016x1.397 smd: 1(-0.95,-1.1) 2(0.95,-1.1) 3(0,1.1)
TP40_SMD
  round 1.016 smd: 1(0,0)
TP_40X80
  round 2.032 hole 1.016: 1(0,0)
unnamed#2
  round 1.016 smd: (0,0)
UQFN10_19-68_80X60_0-6
  rect 0.584x0.305 smd: 1(-0.635,0.75) 4(-0.635,-0.75) 6(0.635,-0.75) 9(0.635,0.75)
  rect 0.584x0.254 smd: 2(-0.637,0.25) 3(-0.637,-0.25) 7(0.637,-0.25) 8(0.637,0.25)
  rect 0.305x0.635 smd: 5(0,-0.86) 10(0,0.86)
USON10_TPD4E05U_40X100_0-6
  rect 0.559x0.305 smd: 1(-0.385,1) 2(-0.385,0.5) 4(-0.385,-0.5) 5(-0.385,-1) 6(0.385,-1) 7(0.385,-0.5) 9(0.385,0.5) 10(0.385,1)
  rect 0.559x0.406 smd: 3(-0.385,0) 8(0.385,0)
XTAL4_86-61X62-99_130X105_SMD_0-6
  rect 1.422x1.219 smd: 1(-1.1,-0.8) 2(1.1,-0.8) 3(1.1,0.8) 4(-1.1,0.8)
XTAL_ABM3_205X130_SMD_1-4
  rect 1.803x2.413 smd: 1(-1.9,0) 2(1.9,0)

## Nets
1V1: C45.1 C46.1 C59.1 C60.1 C61.1 C66.1 C68.1 C71.1 C105.1 C106.1 C107.1 C111.1 FL6.2 U6.8(VDD1P1#8) U6.29(VDD1P1#29) U6.42(VDD1P1#42) U6.58(VDD1P1#58)
1V35: C143.2 C149.2 C167.1 C176.2 C177.1 C187.1 C191.2 C204.1 FL3.2 FL10.1 R69.1 R192.1 R193.1 R211.1 U12.H14(VCCIO2#H14) U12.H15(VCCIO2#H15) U12.J15(VCCIO2#J15) U12.L14(VCCIO3#L14) U12.L15(VCCIO3#L15) U12.L17(PR50B) U12.M15(VCCIO3#M15) U12.P17(PR53D) U12.T18(PR89D/LRC_GPLL0C_MFGOUT2) U12.T20(PR86C) U19.2(VLDOIN)
2V5: C52.1 C54.1 C55.1 C65.1 C67.1 C72.1 C103.1 C108.1 C153.2 C156.1 C158.2 FL1.2 FL9.2 R43.1 R53.1 U5.7(IN1) U5.8(IN2) U6.4(VDDA2P5#4) U6.12(VDDA2P5#12) U8.6(VDD) U12.H6(VCCIO7#H6) U12.H7(VCCIO7#H7) U12.J6(VCCIO7#J6)
2V5_A: C6.1 C42.1 C43.1 FL1.1 L4.2 R11.1
3V3: C7.1 C8.1 C9.1 C22.1 C33.1 C34.1 C35.1 C47.1 C48.1 C56.1 C62.1 C69.1 C70.1 C73.1 C80.2 C82.1 C83.1 C84.2 C87.1 C92.1 C94.1 C98.1 C101.1 C102.1 C104.1 C125.2 C127.2 C131.1 C142.2 C147.1 C166.2 C175.1 C201.1 C202.2 C205.1 C215.1 C216.1 FB1.1 FB2.1 FB3.1 FB4.1 FL4.2 J5.4(VDD) R7.1 R20.1 R28.1 R29.1 R30.1 R31.1 R32.1 R33.1 R34.1 R37.1 R40.1 R50.1 R51.1 R52.1 R55.2 R57.1 R58.1 R64.1 R65.2 R67.1 R68.1 R70.1 R83.1 R87.1 R89.1 R93.1 R103.1 R107.1 R111.1 R115.2 R117.1 R125.1 R131.1 R132.1 R133.2 R134.2 R144.1 R145.1 R147.1 R149.1 R153.1 R154.1 R158.1 R160.1 R162.1 R163.2 R164.2 R165.2 R166.2 R167.2 R168.2 R169.2 R170.2 R171.2 R172.1 R173.1 R174.1 R175.1 R176.1 R177.1 R178.1 R179.1 R180.1 R181.1 R183.1 R184.1 R186.2 R189.2 R201.1 R202.1 R215.1 R216.1 R217.1 R218.1 R219.1 R221.1 R222.2 R223.2 R224.2 TP4.1(TP) U3.20(VCCIO#20) U3.31(VCCIO#31) U3.42(VCCIO#42) U3.50(VREGIN) U3.56(VCCIO#56) U4.6(ORG*) U4.8(VCC) U6.23(VDDIO#23) U6.41(VDDIO#41) U6.57(VDDIO#57) U7.8(VCC) U9.6(VDD) U12.F9(VCCIO0#F9) U12.F10(VCCIO0#F10) U12.F11(VCCIO1#F11) U12.F12(VCCIO1#F12) U12.L6(VCCIO6#L6) U12.L7(VCCIO6#L7) U12.M6(VCCIO6#M6) U12.P9(VCCIO8#P9) U12.P10(VCCIO8#P10) U13.5(VCC) U14.2(VCC) U15.20(VCCIO#20) U15.31(VCCIO#31) U15.42(VCCIO#42) U15.50(VREGIN) U15.56(VCCIO#56) U16.10(VCC) U19.10(VIN) U20.6(ORG*) U20.8(VCC)
